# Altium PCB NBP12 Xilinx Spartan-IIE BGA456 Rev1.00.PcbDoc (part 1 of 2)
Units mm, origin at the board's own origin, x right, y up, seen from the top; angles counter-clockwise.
Board outline 69 x 80.99 mm, 4 copper layers (Top Layer, MidLayer1, InternalPlane1, Bottom Layer); 54 components, 265 nets, 866 pads, 396 vias.
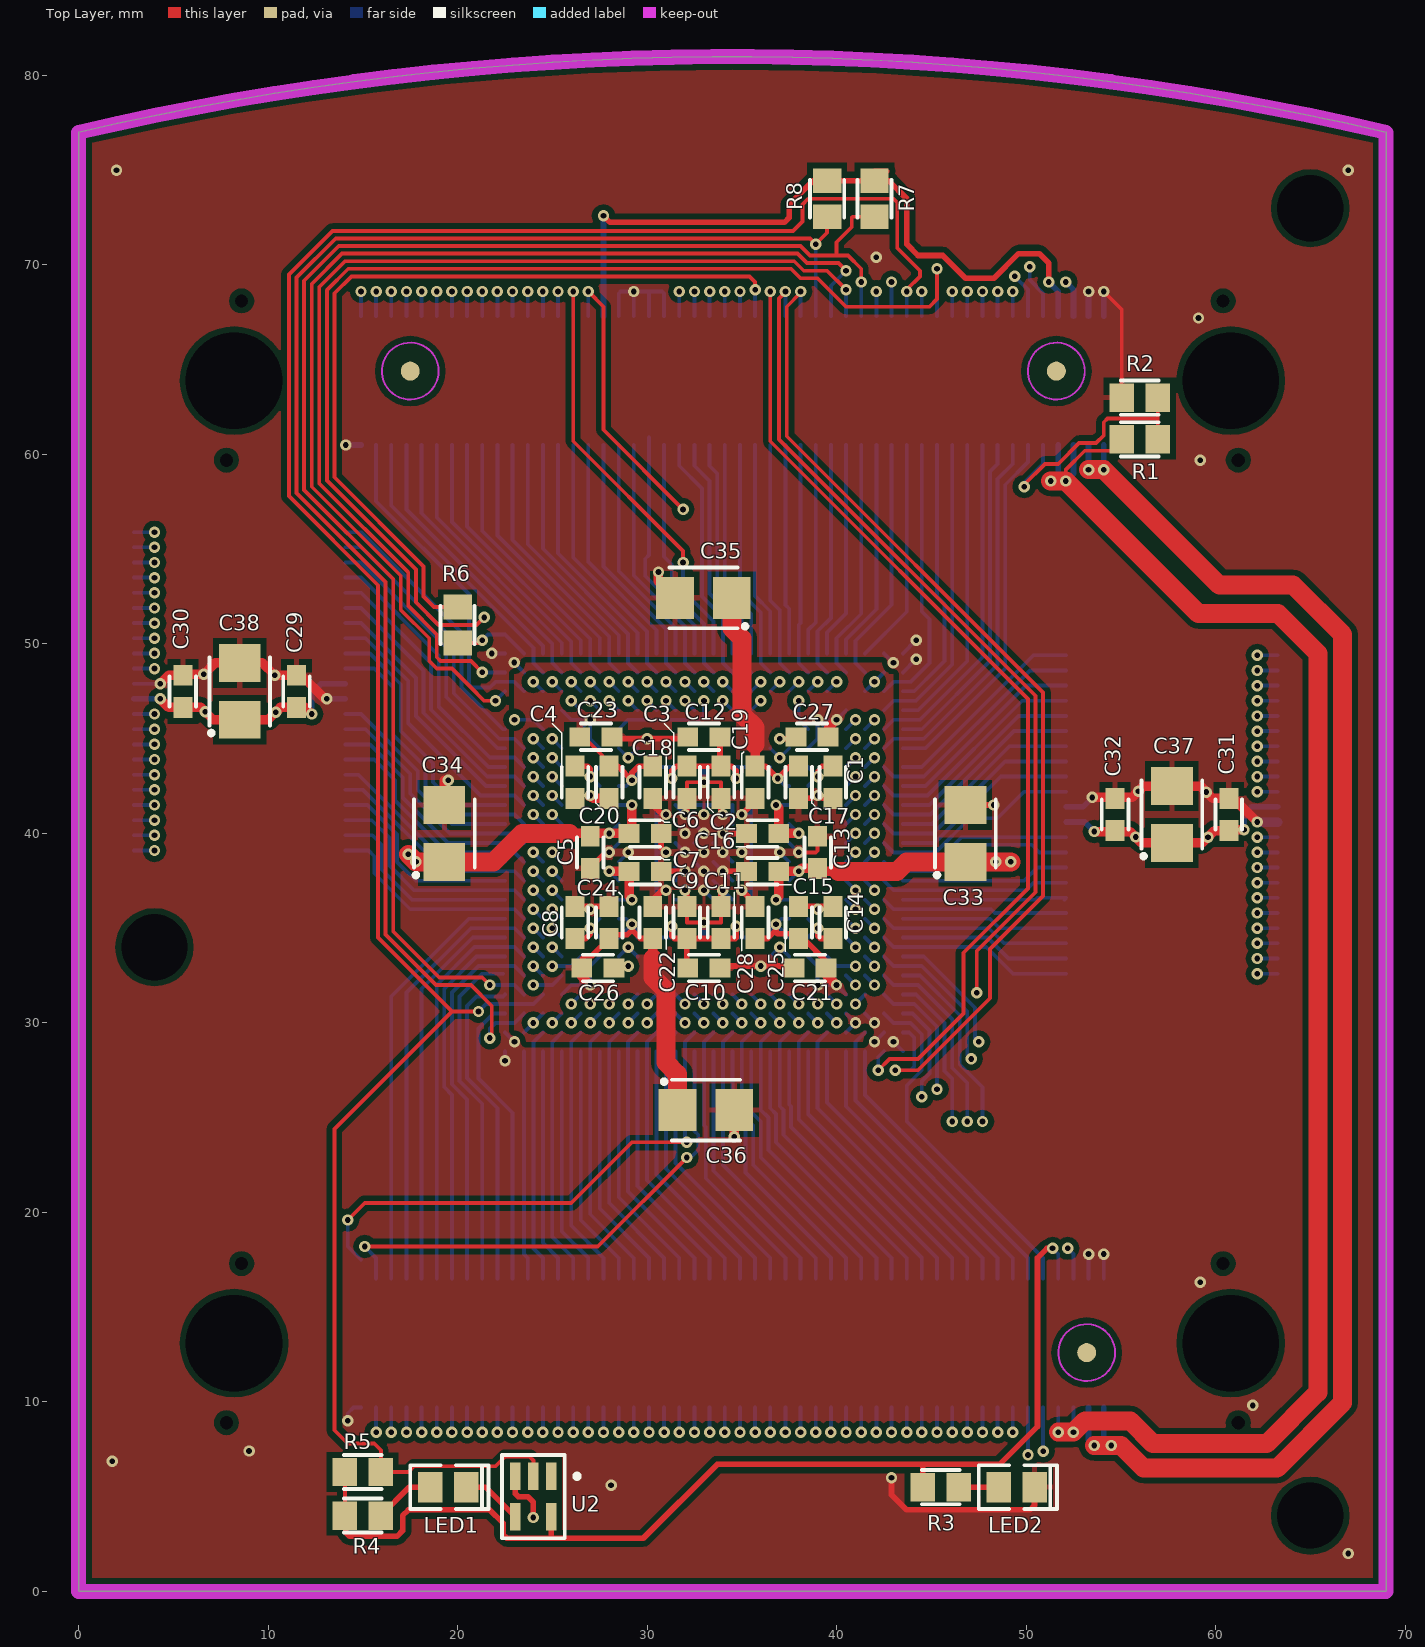
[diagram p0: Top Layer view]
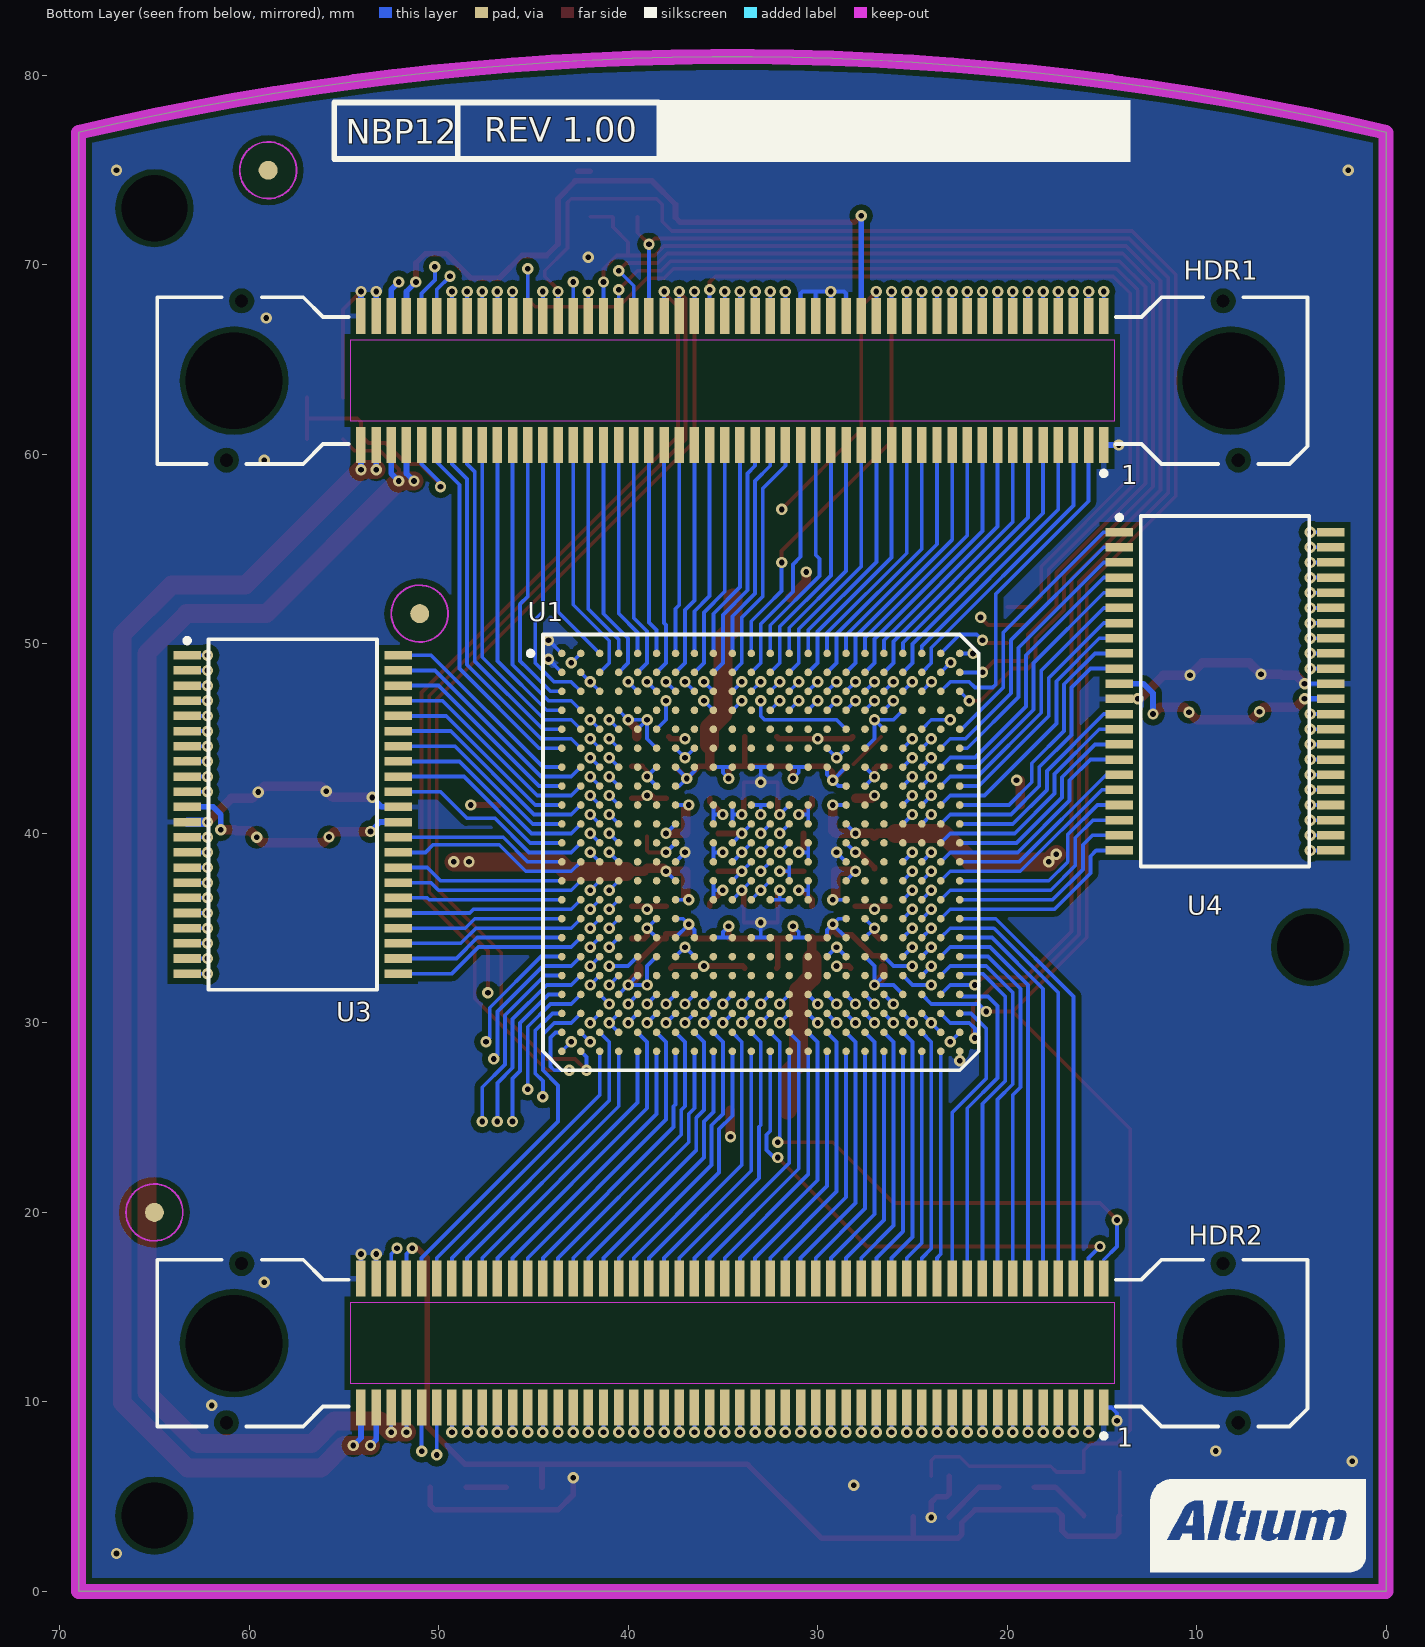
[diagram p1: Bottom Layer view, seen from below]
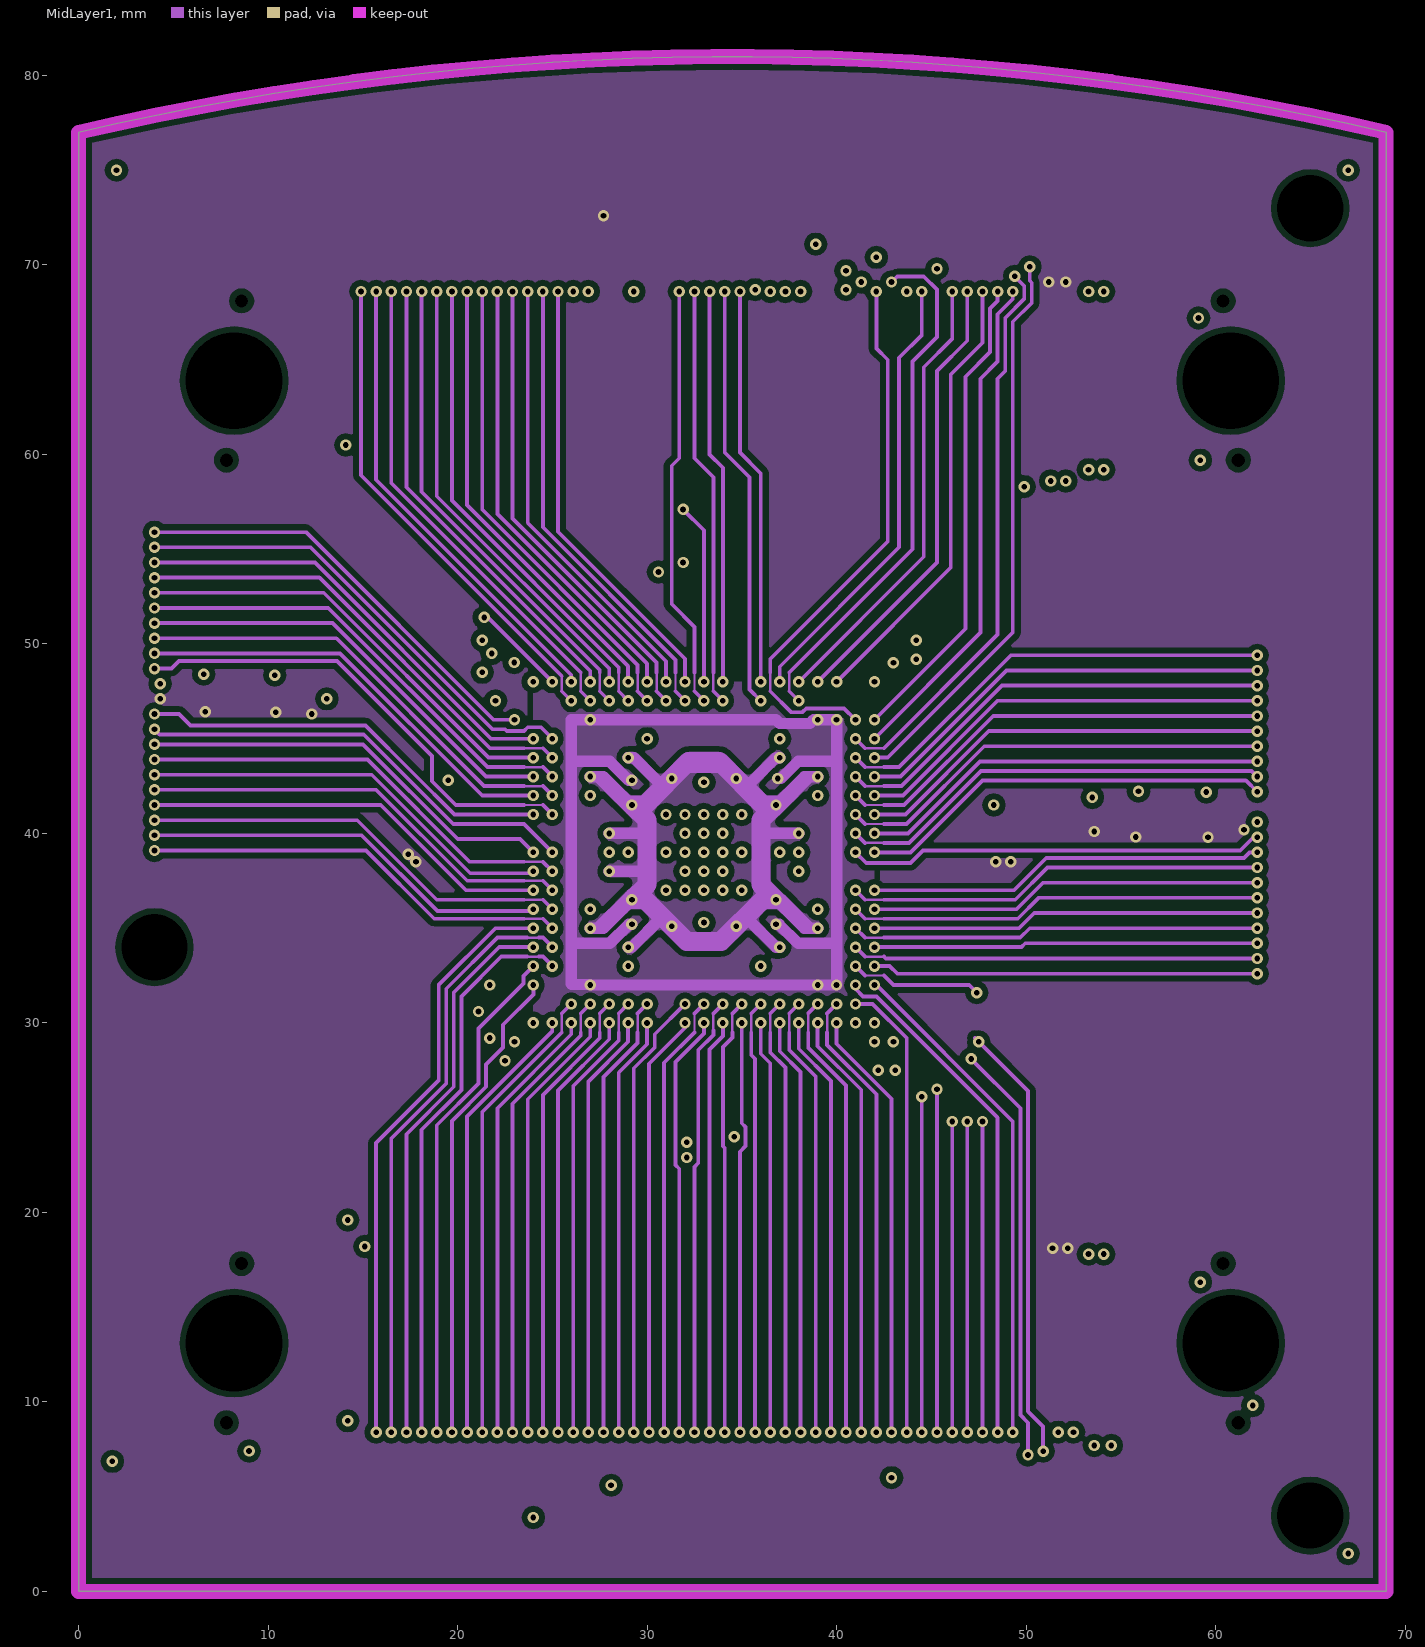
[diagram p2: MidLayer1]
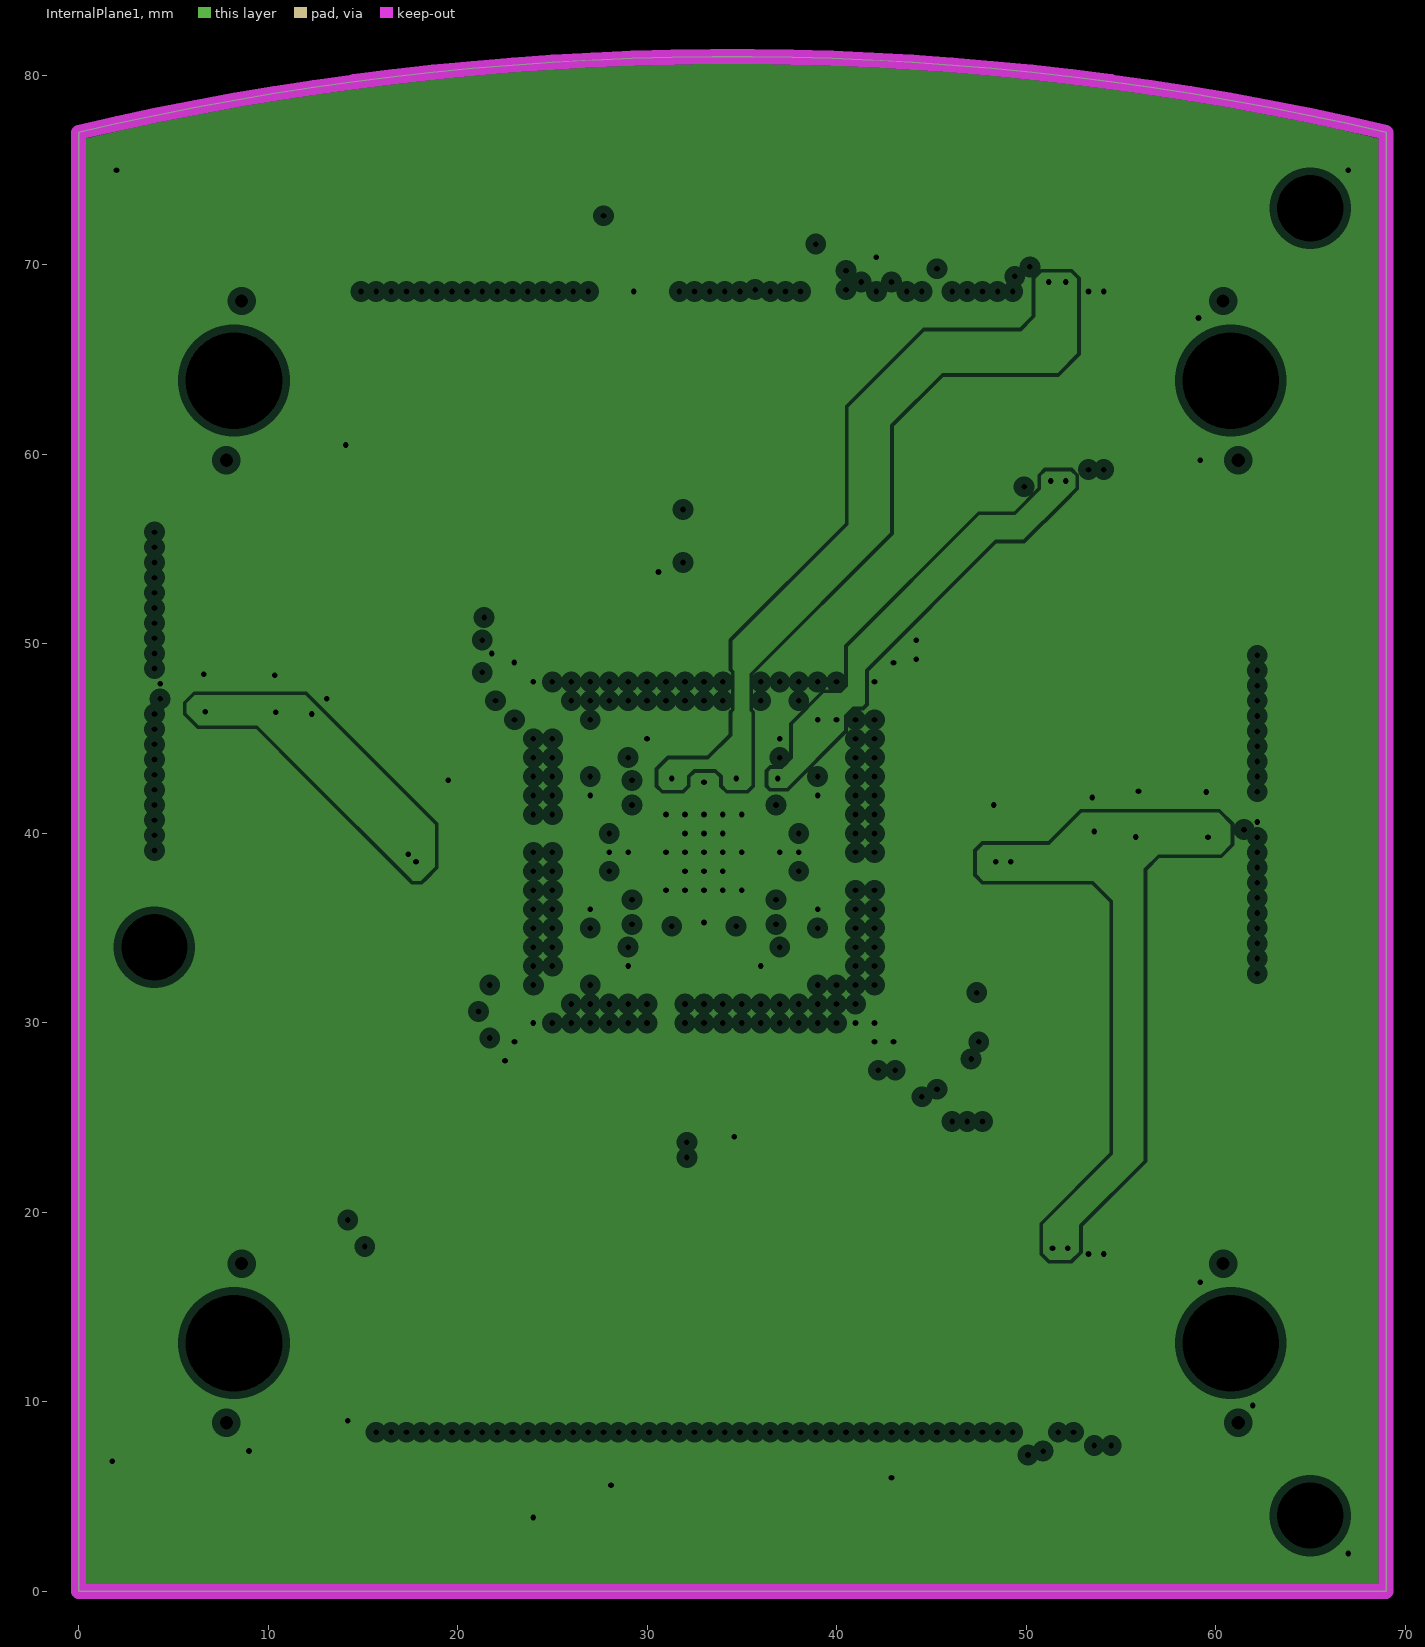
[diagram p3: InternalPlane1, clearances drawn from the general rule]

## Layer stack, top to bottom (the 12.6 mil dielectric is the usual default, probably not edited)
Top Layer: signal copper 0.0356
Dielectric: core 0.32, FR-4, Dk 4.8
MidLayer1: signal copper 0.0356
Dielectric: prepreg 0.32, FR-4, Dk 4.8
InternalPlane1: plane copper 0.0356, net (Multiple Nets)
Dielectric: core 0.32, FR-4, Dk 4.8
Bottom Layer: signal copper 0.0356

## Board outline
0,0 0.001,77 cw(c34.5,-69.801) 69,77 69,0

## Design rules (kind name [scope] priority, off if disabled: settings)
Clearance Clearance_Mid [OnLayer('MidLayer1') and not(InPoly) vs (IsVia)] p1: gap=0.127
Clearance Clearance_Polygons [InPoly] p2: gap=0.3
Clearance Clearance_Std [All] p3: gap=0.2
ComponentClearance [All] p1: gap=0.2 collisioncheckmode=3 verticalgap=0.254 showdistances=FALSE
FabricationTestPointUsage TestPointUsage [All] p1 off: valid=0 allowmultiple=FALSE
FabricationTestpoint Testpoint [All] p1 off: side=3 testpointundercomponent=TRUE minsize=1.016 maxsize=2.54 preferedsize=1.524 minholesize=0 maxholesize=1.016 preferedholesize=0.813 testpointgrid=0.025 allowsidetop=TRUE allowsidebottom=TRUE usegrid=TRUE gridtolerance=0
HoleSize [All] p1: absolutevalues=TRUE maxlimit=5.2 minlimit=0.25 maxpercent=80.000 minpercent=20.000
MinimumAnnularRing [not inpadclass('Mounting Holes')] p1: minimumring=0.051
PlaneClearance [All] p1: clearance=0.4
PlaneConnect [All] p1: planeconnectstyle=Direct reliefexpansion=0.2 reliefentries=4 reliefconductorwidth=0.2 reliefairgap=0.2
PolygonConnect FPGA_Connect [(InComponent('U1') AND InNet('GND'))] p1: connectstyle=NoConnect reliefconductorwidth=0.254 reliefentries=4 polygonreliefangle="90 Angle"
PolygonConnect [All] p2: connectstyle=Relief reliefconductorwidth=0.3 reliefentries=4 polygonreliefangle="90 Angle"
RoutingLayers [All] p1: top layer_v5=TRUE mid layer 1_v5=FALSE bottom layer_v5=TRUE
RoutingVias [All] p1: holewidth=0.3 width=0.6 viastyle="Through Hole" minholewidth=0.3 minwidth=0.6 maxholewidth=0.5 maxwidth=0.9
SMDNeckDown [All] p1: percent=100.000
SilkscreenOverComponentPads [All] p1: minsilkscreentomaskgap=0.254
SolderMaskExpansion SolderMaskExpansion_Vias [IsVia] p1: expansion=-0.15
SolderMaskExpansion [All] p2: expansion=0.1
Width Width_Arc [isarc] p1: maxlimit=0.8 minlimit=0.1 preferedwidth=0.1
Width [All] p2: maxlimit=1.5 minlimit=0.127 preferedwidth=0.2
20 further rules are at their usual default settings.

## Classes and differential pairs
pad class "Mounting Holes": Free-LP HDR1-MH1 HDR1-MH2 HDR1-MH3 HDR1-MH4 HDR1-MH5 HDR1-MH6 HDR2-MH1 HDR2-MH2 HDR2-MH3 HDR2-MH4 HDR2-MH5 HDR2-MH6

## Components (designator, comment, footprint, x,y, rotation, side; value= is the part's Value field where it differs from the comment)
C1 "0.1uF" CC1608-0603 39.8,42.7 r90 top
C2 "0.1uF" CC1608-0603 33.9,42.7 r90 top
C3 "0.1uF" CC1608-0603 32.1,42.7 r90 top
C4 "0.1uF" CC1608-0603 26.2,42.7 r90 top
C5 "0.1uF" CC1608-0603 27,39 r90 top
C6 "0.1uF" CC1608-0603 29.9,40 r180 top
C7 "0.1uF" CC1608-0603 29.9,38 r180 top
C8 "0.1uF" CC1608-0603 26.2,35.3 r270 top
C9 "0.1uF" CC1608-0603 32.1,35.3 r270 top
C10 "0.1uF" CC1608-0603 33,32.9 r180 top
C11 "0.1uF" CC1608-0603 33.9,35.3 r270 top
C12 "0.1uF" CC1608-0603 33,45.1 r0 top
C13 "0.1uF" CC1608-0603 39,39 r270 top
C14 "0.1uF" CC1608-0603 39.8,35.3 r270 top
C15 "0.1uF" CC1608-0603 36.1,38 r0 top
C16 "0.1uF" CC1608-0603 36.1,40 r0 top
C17 "0.1uF" CC1608-0603 38,42.7 r90 top
C18 "0.1uF" CC1608-0603 30.3,42.7 r90 top
C19 "0.1uF" CC1608-0603 35.7,42.7 r90 top
C20 "0.1uF" CC1608-0603 28,42.7 r90 top
C21 "0.1uF" CC1608-0603 38.6,32.9 r0 top
C22 "0.1uF" CC1608-0603 30.3,35.3 r270 top
C23 "0.1uF" CC1608-0603 27.3,45.1 r180 top
C24 "0.1uF" CC1608-0603 28,35.3 r270 top
C25 "0.1uF" CC1608-0603 38,35.3 r270 top
C26 "0.1uF" CC1608-0603 27.4,32.9 r180 top
C27 "0.1uF" CC1608-0603 38.7,45.1 r0 top
C28 "0.1uF" CC1608-0603 35.7,35.3 r270 top
C29 "0.1uF" CC1608-0603 11.5,47.5 r270 top
C30 "0.1uF" CC1608-0603 5.5,47.5 r270 top
C31 "0.1uF" CC1608-0603 60.7,41 r270 top
C32 "0.1uF" CC1608-0603 54.7,41 r270 top
C33 "10uF" MCCT-B 46.8,40 r90 top
C34 "10uF" MCCT-B 19.3,40 r90 top
C35 "10uF" MCCT-B 32.971,52.429 r180 top
C36 "10uF" MCCT-B 33.1,25.4 r0 top
C37 "10uF" MCCT-B 57.7,41 r90 top
C38 "10uF" MCCT-B 8.5,47.5 r90 top
HDR1 "54075-1009" 54075 34.5,63.9 r0 bottom locked
HDR2 "54075-1009" 54075 34.5,13.1 r0 bottom locked
LED1 "HSMG-C670" "SMD _LED" 19.5,5.5 r180 top locked
LED2 "HSMH-C670" "SMD _LED" 49.5,5.5 r180 top locked
R1 "DO NOT INSTALL" CC2012-0805#1 56,60.8 r0 top
R2 "DO NOT INSTALL" CC2012-0805#1 56,63 r180 top
R3 "270R" CC2012-0805#1 45.5,5.5 r0 top
R4 "270R" CC2012-0805#1 15,4 r0 top
R5 "4K7" CC2012-0805#1 15,6.3 r0 top
R6 "100R" CC2012-0805#2 20,51 r90 top
R7 "4K7" CC2012-0805#1 42,73.5 r270 top
R8 "4K7" CC2012-0805#1 39.5,73.5 r270 top
U1 "XC2S600E-6FG456C" FG456 33,39 r180 bottom locked
U2 "SN74AHC1G04DBVR" SO-G5/P.95 24,5 r180 top
U3 "SRAM 512Kx16 TSOP44" SO-G44/P.8 57.7,41 r270 bottom
U4 "SRAM 512Kx16 TSOP44" SO-G44/P.8 8.5,47.5 r270 bottom locked

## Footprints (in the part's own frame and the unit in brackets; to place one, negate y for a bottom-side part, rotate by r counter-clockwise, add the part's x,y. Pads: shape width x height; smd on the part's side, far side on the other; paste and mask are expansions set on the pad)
54075 [mm] "Connector; Docking Station, Receptacle; 100 Position; Vertical"
  rect 0.5x1.9 smd: 1(-19.6,3.4) 2(-19.6,-3.4) 3(-18.8,3.4) 4(-18.8,-3.4) 5(-18,3.4) 6(-18,-3.4) 7(-17.2,3.4) 8(-17.2,-3.4) 9(-16.4,3.4) 10(-16.4,-3.4) 11(-15.6,3.4) 12(-15.6,-3.4) 13(-14.8,3.4) 14(-14.8,-3.4) 15(-14,3.4) 16(-14,-3.4) 17(-13.2,3.4) 18(-13.2,-3.4) 19(-12.4,3.4) 20(-12.4,-3.4) 21(-11.6,3.4) 22(-11.6,-3.4) 23(-10.8,3.4) 24(-10.8,-3.4) 25(-10,3.4) 26(-10,-3.4) 27(-9.2,3.4) 28(-9.2,-3.4) 29(-8.4,3.4) 30(-8.4,-3.4) 31(-7.6,3.4) 32(-7.6,-3.4) 33(-6.8,3.4) 34(-6.8,-3.4) 35(-6,3.4) 36(-6,-3.4) 37(-5.2,3.4) 38(-5.2,-3.4) 39(-4.4,3.4) 40(-4.4,-3.4) 41(-3.6,3.4) 42(-3.6,-3.4) 43(-2.8,3.4) 44(-2.8,-3.4) 45(-2,3.4) 46(-2,-3.4) 47(-1.2,3.4) 48(-1.2,-3.4) 49(-0.4,3.4) 50(-0.4,-3.4) 51(0.4,3.4) 52(0.4,-3.4) 53(1.2,3.4) 54(1.2,-3.4) 55(2,3.4) 56(2,-3.4) 57(2.8,3.4) 58(2.8,-3.4) 59(3.6,3.4) 60(3.6,-3.4) 61(4.4,3.4) 62(4.4,-3.4) 63(5.2,3.4) 64(5.2,-3.4) 65(6,3.4) 66(6,-3.4) 67(6.8,3.4) 68(6.8,-3.4) 69(7.6,3.4) 70(7.6,-3.4) 71(8.4,3.4) 72(8.4,-3.4) 73(9.2,3.4) 74(9.2,-3.4) 75(10,3.4) 76(10,-3.4) 77(10.8,3.4) 78(10.8,-3.4) 79(11.6,3.4) 80(11.6,-3.4) 81(12.4,3.4) 82(12.4,-3.4) 83(13.2,3.4) 84(13.2,-3.4) 85(14,3.4) 86(14,-3.4) 87(14.8,3.4) 88(14.8,-3.4) 89(15.6,3.4) 90(15.6,-3.4) 91(16.4,3.4) 92(16.4,-3.4) 93(17.2,3.4) 94(17.2,-3.4) 95(18,3.4) 96(18,-3.4) 97(18.8,3.4) 98(18.8,-3.4) 99(19.6,3.4) 100(19.6,-3.4)
  round 0.5 hole 0.7 unplated: MH1(-26.7,4.2) MH2(-25.9,-4.2) MH3(26.7,4.2) MH4(25.9,-4.2)
  round 4.8 hole 5.1 unplated: MH5(-26.3,0) MH6(26.3,0)
  Top Layer keep-out region: -20.15,2.15 20.15,2.15 20.15,-2.15 -20.15,-2.15
  silkscreen extent -30.35,-4.4 30.35,5.02
CC1608-0603 [mm]
  rect 1.1x1 smd: 1(-0.85,0) 2(0.85,0)
  silkscreen extent -0.8,-0.7 0.8,0.7
CC2012-0805#1 [mm]
  rect 1.3x1.5 smd: 1(-0.95,0) 2(0.95,0)
  silkscreen extent -1,-0.9 1,0.9
CC2012-0805#2 [mm]
  rect 1.3x1.5 smd: 1(-0.95,0.003) 2(0.95,0.003)
  silkscreen extent -1,-0.9 1,0.9
FG456 [mm] "456-Ball Fine Pitch Ball Grid Array (FG456)"
  round 0.4 smd: A1(-10.5,10.5) A2(-9.5,10.5) A3(-8.5,10.5) A4(-7.5,10.5) A5(-6.5,10.5) A6(-5.5,10.5) A7(-4.5,10.5) A8(-3.5,10.5) A9(-2.5,10.5) A10(-1.5,10.5) A11(-0.5,10.5) A12(0.5,10.5) A13(1.5,10.5) A14(2.5,10.5) A15(3.5,10.5) A16(4.5,10.5) A17(5.5,10.5) A18(6.5,10.5) A19(7.5,10.5) A20(8.5,10.5) A21(9.5,10.5) A22(10.5,10.5) AA1(-10.5,-9.5) AA2(-9.5,-9.5) AA3(-8.5,-9.5) AA4(-7.5,-9.5) AA5(-6.5,-9.5) AA6(-5.5,-9.5) AA7(-4.5,-9.5) AA8(-3.5,-9.5) AA9(-2.5,-9.5) AA10(-1.5,-9.5) AA11(-0.5,-9.5) AA12(0.5,-9.5) AA13(1.5,-9.5) AA14(2.5,-9.5) AA15(3.5,-9.5) AA16(4.5,-9.5) AA17(5.5,-9.5) AA18(6.5,-9.5) AA19(7.5,-9.5) AA20(8.5,-9.5) AA21(9.5,-9.5) AA22(10.5,-9.5) AB1(-10.5,-10.5) AB2(-9.5,-10.5) AB3(-8.5,-10.5) AB4(-7.5,-10.5) AB5(-6.5,-10.5) AB6(-5.5,-10.5) AB7(-4.5,-10.5) AB8(-3.5,-10.5) AB9(-2.5,-10.5) AB10(-1.5,-10.5) AB11(-0.5,-10.5) AB12(0.5,-10.5) AB13(1.5,-10.5) AB14(2.5,-10.5) AB15(3.5,-10.5) AB16(4.5,-10.5) AB17(5.5,-10.5) AB18(6.5,-10.5) AB19(7.5,-10.5) AB20(8.5,-10.5) AB21(9.5,-10.5) AB22(10.5,-10.5) B1(-10.5,9.5) B2(-9.5,9.5) B3(-8.5,9.5) B4(-7.5,9.5) B5(-6.5,9.5) B6(-5.5,9.5) B7(-4.5,9.5) B8(-3.5,9.5) B9(-2.5,9.5) B10(-1.5,9.5) B11(-0.5,9.5) B12(0.5,9.5) B13(1.5,9.5) B14(2.5,9.5) B15(3.5,9.5) B16(4.5,9.5) B17(5.5,9.5) B18(6.5,9.5) B19(7.5,9.5) B20(8.5,9.5) B21(9.5,9.5) B22(10.5,9.5) C1(-10.5,8.5) C2(-9.5,8.5) C3(-8.5,8.5) C4(-7.5,8.5) C5(-6.5,8.5) C6(-5.5,8.5) C7(-4.5,8.5) C8(-3.5,8.5) C9(-2.5,8.5) C10(-1.5,8.5) C11(-0.5,8.5) C12(0.5,8.5) C13(1.5,8.5) C14(2.5,8.5) C15(3.5,8.5) C16(4.5,8.5) C17(5.5,8.5) C18(6.5,8.5) C19(7.5,8.5) C20(8.5,8.5) C21(9.5,8.5) C22(10.5,8.5) D1(-10.5,7.5) D2(-9.5,7.5) D3(-8.5,7.5) D4(-7.5,7.5) D5(-6.5,7.5) D6(-5.5,7.5) D7(-4.5,7.5) D8(-3.5,7.5) D9(-2.5,7.5) D10(-1.5,7.5) D11(-0.5,7.5) D12(0.5,7.5) D13(1.5,7.5) D14(2.5,7.5) D15(3.5,7.5) D16(4.5,7.5) D17(5.5,7.5) D18(6.5,7.5) D19(7.5,7.5) D20(8.5,7.5) D21(9.5,7.5) D22(10.5,7.5) E1(-10.5,6.5) E2(-9.5,6.5) E3(-8.5,6.5) E4(-7.5,6.5) E5(-6.5,6.5) E6(-5.5,6.5) E7(-4.5,6.5) E8(-3.5,6.5) E9(-2.5,6.5) E10(-1.5,6.5) E11(-0.5,6.5) E12(0.5,6.5) E13(1.5,6.5) E14(2.5,6.5) E15(3.5,6.5) E16(4.5,6.5) E17(5.5,6.5) E18(6.5,6.5) E19(7.5,6.5) E20(8.5,6.5) E21(9.5,6.5) E22(10.5,6.5) F1(-10.5,5.5) F2(-9.5,5.5) F3(-8.5,5.5) F4(-7.5,5.5) F5(-6.5,5.5) F6(-5.5,5.5) F7(-4.5,5.5) F8(-3.5,5.5) F9(-2.5,5.5) F10(-1.5,5.5) F11(-0.5,5.5) F12(0.5,5.5) F13(1.5,5.5) F14(2.5,5.5) F15(3.5,5.5) F16(4.5,5.5) F17(5.5,5.5) F18(6.5,5.5) F19(7.5,5.5) F20(8.5,5.5) F21(9.5,5.5) F22(10.5,5.5) G1(-10.5,4.5) G2(-9.5,4.5) G3(-8.5,4.5) G4(-7.5,4.5) G5(-6.5,4.5) G6(-5.5,4.5) G7(-4.5,4.5) G8(-3.5,4.5) G9(-2.5,4.5) G10(-1.5,4.5) G11(-0.5,4.5) G12(0.5,4.5) G13(1.5,4.5) G14(2.5,4.5) G15(3.5,4.5) G16(4.5,4.5) G17(5.5,4.5) G18(6.5,4.5) G19(7.5,4.5) G20(8.5,4.5) G21(9.5,4.5) G22(10.5,4.5) H1(-10.5,3.5) H2(-9.5,3.5) H3(-8.5,3.5) H4(-7.5,3.5) H5(-6.5,3.5) H6(-5.5,3.5) H7(-4.5,3.5) H16(4.5,3.5) H17(5.5,3.5) H18(6.5,3.5) H19(7.5,3.5) H20(8.5,3.5) H21(9.5,3.5) H22(10.5,3.5) J1(-10.5,2.5) J2(-9.5,2.5) J3(-8.5,2.5) J4(-7.5,2.5) J5(-6.5,2.5) J6(-5.5,2.5) J7(-4.5,2.5) J9(-2.5,2.5) J10(-1.5,2.5) J11(-0.5,2.5) J12(0.5,2.5) J13(1.5,2.5) J14(2.5,2.5) J16(4.5,2.5) J17(5.5,2.5) J18(6.5,2.5) J19(7.5,2.5) J20(8.5,2.5) J21(9.5,2.5) J22(10.5,2.5) K1(-10.5,1.5) K2(-9.5,1.5) K3(-8.5,1.5) K4(-7.5,1.5) K5(-6.5,1.5) K6(-5.5,1.5) K7(-4.5,1.5) K9(-2.5,1.5) K10(-1.5,1.5) K11(-0.5,1.5) K12(0.5,1.5) K13(1.5,1.5) K14(2.5,1.5) K16(4.5,1.5) K17(5.5,1.5) K18(6.5,1.5) K19(7.5,1.5) K20(8.5,1.5) K21(9.5,1.5) K22(10.5,1.5) L1(-10.5,0.5) L2(-9.5,0.5) L3(-8.5,0.5) L4(-7.5,0.5) L5(-6.5,0.5) L6(-5.5,0.5) L7(-4.5,0.5) L9(-2.5,0.5) L10(-1.5,0.5) L11(-0.5,0.5) L12(0.5,0.5) L13(1.5,0.5) L14(2.5,0.5) L16(4.5,0.5) L17(5.5,0.5) L18(6.5,0.5) L19(7.5,0.5) L20(8.5,0.5) L21(9.5,0.5) L22(10.5,0.5) M1(-10.5,-0.5) M2(-9.5,-0.5) M3(-8.5,-0.5) M4(-7.5,-0.5) M5(-6.5,-0.5) M6(-5.5,-0.5) M7(-4.5,-0.5) M9(-2.5,-0.5) M10(-1.5,-0.5) M11(-0.5,-0.5) M12(0.5,-0.5) M13(1.5,-0.5) M14(2.5,-0.5) M16(4.5,-0.5) M17(5.5,-0.5) M18(6.5,-0.5) M19(7.5,-0.5) M20(8.5,-0.5) M21(9.5,-0.5) M22(10.5,-0.5) N1(-10.5,-1.5) N2(-9.5,-1.5) N3(-8.5,-1.5) N4(-7.5,-1.5) N5(-6.5,-1.5) N6(-5.5,-1.5) N7(-4.5,-1.5) N9(-2.5,-1.5) N10(-1.5,-1.5) N11(-0.5,-1.5) N12(0.5,-1.5) N13(1.5,-1.5) N14(2.5,-1.5) N16(4.5,-1.5) N17(5.5,-1.5) N18(6.5,-1.5) N19(7.5,-1.5) N20(8.5,-1.5) N21(9.5,-1.5) N22(10.5,-1.5) P1(-10.5,-2.5) P2(-9.5,-2.5) P3(-8.5,-2.5) P4(-7.5,-2.5) P5(-6.5,-2.5) P6(-5.5,-2.5) P7(-4.5,-2.5) P9(-2.5,-2.5) P10(-1.5,-2.5) P11(-0.5,-2.5) P12(0.5,-2.5) P13(1.5,-2.5) P14(2.5,-2.5) P16(4.5,-2.5) P17(5.5,-2.5) P18(6.5,-2.5) P19(7.5,-2.5) P20(8.5,-2.5) P21(9.5,-2.5) P22(10.5,-2.5) R1(-10.5,-3.5) R2(-9.5,-3.5) R3(-8.5,-3.5) R4(-7.5,-3.5) R5(-6.5,-3.5) R6(-5.5,-3.5) R7(-4.5,-3.5) R16(4.5,-3.5) R17(5.5,-3.5) R18(6.5,-3.5) R19(7.5,-3.5) R20(8.5,-3.5) R21(9.5,-3.5) R22(10.5,-3.5) T1(-10.5,-4.5) T2(-9.5,-4.5) T3(-8.5,-4.5) T4(-7.5,-4.5) T5(-6.5,-4.5) T6(-5.5,-4.5) T7(-4.5,-4.5) T8(-3.5,-4.5) T9(-2.5,-4.5) T10(-1.5,-4.5) T11(-0.5,-4.5) T12(0.5,-4.5) T13(1.5,-4.5) T14(2.5,-4.5) T15(3.5,-4.5) T16(4.5,-4.5) T17(5.5,-4.5) T18(6.5,-4.5) T19(7.5,-4.5) T20(8.5,-4.5) T21(9.5,-4.5) T22(10.5,-4.5) U1(-10.5,-5.5) U2(-9.5,-5.5) U3(-8.5,-5.5) U4(-7.5,-5.5) U5(-6.5,-5.5) U6(-5.5,-5.5) U7(-4.5,-5.5) U8(-3.5,-5.5) U9(-2.5,-5.5) U10(-1.5,-5.5) U11(-0.5,-5.5) U12(0.5,-5.5) U13(1.5,-5.5) U14(2.5,-5.5) U15(3.5,-5.5) U16(4.5,-5.5) U17(5.5,-5.5) U18(6.5,-5.5) U19(7.5,-5.5) U20(8.5,-5.5) U21(9.5,-5.5) U22(10.5,-5.5) V1(-10.5,-6.5) V2(-9.5,-6.5) V3(-8.5,-6.5) V4(-7.5,-6.5) V5(-6.5,-6.5) V6(-5.5,-6.5) V7(-4.5,-6.5) V8(-3.5,-6.5) V9(-2.5,-6.5) V10(-1.5,-6.5) V11(-0.5,-6.5) V12(0.5,-6.5) V13(1.5,-6.5) V14(2.5,-6.5) V15(3.5,-6.5) V16(4.5,-6.5) V17(5.5,-6.5) V18(6.5,-6.5) V19(7.5,-6.5) V20(8.5,-6.5) V21(9.5,-6.5) V22(10.5,-6.5) W1(-10.5,-7.5) W2(-9.5,-7.5) W3(-8.5,-7.5) W4(-7.5,-7.5) W5(-6.5,-7.5) W6(-5.5,-7.5) W7(-4.5,-7.5) W8(-3.5,-7.5) W9(-2.5,-7.5) W10(-1.5,-7.5) W11(-0.5,-7.5) W12(0.5,-7.5) W13(1.5,-7.5) W14(2.5,-7.5) W15(3.5,-7.5) W16(4.5,-7.5) W17(5.5,-7.5) W18(6.5,-7.5) W19(7.5,-7.5) W20(8.5,-7.5) W21(9.5,-7.5) W22(10.5,-7.5) Y1(-10.5,-8.5) Y2(-9.5,-8.5) Y3(-8.5,-8.5) Y4(-7.5,-8.5) Y5(-6.5,-8.5) Y6(-5.5,-8.5) Y7(-4.5,-8.5) Y8(-3.5,-8.5) Y9(-2.5,-8.5) Y10(-1.5,-8.5) Y11(-0.5,-8.5) Y12(0.5,-8.5) Y13(1.5,-8.5) Y14(2.5,-8.5) Y15(3.5,-8.5) Y16(4.5,-8.5) Y17(5.5,-8.5) Y18(6.5,-8.5) Y19(7.5,-8.5) Y20(8.5,-8.5) Y21(9.5,-8.5) Y22(10.5,-8.5)
  silkscreen extent -12.28,-11.5 11.5,11.5
MCCT-B [mm]
  rect 2x2.2 smd: 1(-1.5,0) 2(1.5,0)
  silkscreen extent -2.3,-1.6 1.8,1.6
"SMD _LED" [mm]
  rect 1.3x1.6 smd: 1(0.95,0) 2(-0.95,0)
  silkscreen extent -2.13,-1.15 2,1.15
SO-G5/P.95 [mm]
  rect 0.55x1.45 smd: 1(-0.95,-1.075) 2(0,-1.075) 3(0.95,-1.075) 4(0.95,1.075) 5(-0.95,1.075)
  silkscreen extent -2.43,-2.2 1.65,2.2
SO-G44/P.8 [mm]
  rect 0.45x1.45 smd: 1(-8.4,-5.575) 2(-7.6,-5.575) 3(-6.8,-5.575) 4(-6,-5.575) 5(-5.2,-5.575) 6(-4.4,-5.575) 7(-3.6,-5.575) 8(-2.8,-5.575) 9(-2,-5.575) 10(-1.2,-5.575) 11(-0.4,-5.575) 12(0.4,-5.575) 13(1.2,-5.575) 14(2,-5.575) 15(2.8,-5.575) 16(3.6,-5.575) 17(4.4,-5.575) 18(5.2,-5.575) 19(6,-5.575) 20(6.8,-5.575) 21(7.6,-5.575) 22(8.4,-5.575) 23(8.4,5.575) 24(7.6,5.575) 25(6.8,5.575) 26(6,5.575) 27(5.2,5.575) 28(4.4,5.575) 29(3.6,5.575) 30(2.8,5.575) 31(2,5.575) 32(1.2,5.575) 33(0.4,5.575) 34(-0.4,5.575) 35(-1.2,5.575) 36(-2,5.575) 37(-2.8,5.575) 38(-3.6,5.575) 39(-4.4,5.575) 40(-5.2,5.575) 41(-6,5.575) 42(-6.8,5.575) 43(-7.6,5.575) 44(-8.4,5.575)
  silkscreen extent -9.3,-5.7 9.25,4.45

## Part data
C1 C2 C3 C4 C5 C6 C7 C8 C9 C10 C11 C12 C13 C14 C15 C16 C17 C18 C19 C20 C21 C22 C23 C24 C25 C26 C27 C28 C29 C30 C31 C32: library part CAP, "Capacitor"
C33 C34 C35 C36 C37 C38: library part CAP_POLAR, "Polar Capacitor"
HDR1 HDR2: "Board-to-Board, Docking Station, 0.80mm (.031\") Pitch, Shielded Receptacle, Vertical, Ultra Low Profile, SMT"
LED1: library part HSMX-C670, "GREEN AS AlGaAs SMD LED"
LED2: library part HSMX-C670, "RED AS AlGaAs SMD LED"
R1 R2 R3 R4 R5 R6 R7 R8: library part RES, "Resistor"
U1: "Spartan-IIE 1.8V FPGA, 456-Ball FBGA, Standard Performance, Commercial Grade"
U2: "Single Gate Inverter"
U3 U4: "512Kx16Bit SRAM TSOP44"

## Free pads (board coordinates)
  round 1 smd far side mask+1: FID1(59,75) FID2(51,51.6) FID3(65,20)
  round 1 smd mask+1: FID5(17.5,64.4) FID6(51.6,64.4) FID7(53.2,12.6)
  round 3.2 hole 3.5 unplated: LP(4,34) LP(65,4) LP(65,73)

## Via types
v1: diameter 0.6, hole 0.3, Top Layer to Bottom Layer, tented top, 396 vias

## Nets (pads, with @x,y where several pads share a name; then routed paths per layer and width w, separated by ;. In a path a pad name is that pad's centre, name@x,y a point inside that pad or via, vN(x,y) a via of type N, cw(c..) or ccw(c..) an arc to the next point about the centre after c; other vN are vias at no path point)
5V: HDR1.97 HDR1.99 HDR2.97 HDR2.99 | length 79.5
  Top Layer w1: v1(53.3,59.2) v1(54.1,59.2) 60.2,53.1 64.1,53.1 66.7,50.5 66.7,9.954 63.246,6.5 56.2,6.5 55,7.7 v1(53.6,7.7)
  Bottom Layer w0.3: HDR2.97@53.3,9.7 53.3,8 v1(53.6,7.7) ; v1(53.3,59.2) HDR1.97@53.3,60.5 ; HDR2.99@54.1,9.7 54.1,8.1 v1(54.5,7.7) ; v1(54.1,59.2) HDR1.99@54.1,60.5
AUDIO_SPI_CSN: HDR1.11 U1.A19 | length 13.7
  Bottom Layer w0.2: HDR1.11@18.9,60.5 18.9,56.666 25.5,50.066 U1.A19@25.5,49.5
BLUE0: HDR1.14 U1.D15 | length 27.5
  MidLayer1 w0.127: 28.5,47.5 28.5,48.5
  MidLayer1 w0.2: v1(19.7,68.6) 19.7,57.563 28.5,48.763 28.5,48.5 ; 28.5,47.5 v1(29,47)
  Bottom Layer w0.2: HDR1.14@19.7,67.3 v1(19.7,68.6) ; v1(29,47) U1.D15@29.5,46.5
BLUE1: HDR1.16 U1.C15 | length 26.1
  MidLayer1 w0.2: v1(20.5,68.6) 20.5,57.328 29,48.828 v1(29,48)
  Bottom Layer w0.2: HDR1.16@20.5,67.3 v1(20.5,68.6) ; v1(29,48) U1.C15@29.5,47.5
BOC_CTS: HDR1.13 U1.B18 | length 14.8
  Bottom Layer w0.2: HDR1.13@19.7,60.5 19.7,56.431 26,50.131 26,49 U1.B18@26.5,48.5
BOC_RTS: HDR1.17 U1.B17 | length 14.6
  Bottom Layer w0.2: HDR1.17@21.3,60.5 21.3,55.963 27,50.263 27,49 U1.B17@27.5,48.5
BOC_RX: HDR1.19 U1.A17 | length 13.2
  Bottom Layer w0.2: HDR1.19@22.1,60.5 22.1,55.728 27.5,50.328 U1.A17@27.5,49.5
BOC_TX: HDR1.15 U1.A18 | length 13.5
  Bottom Layer w0.2: HDR1.15@20.5,60.5 20.5,56.197 26.5,50.197 U1.A18@26.5,49.5
BUZZER: HDR2.24 U1.AB21 | length 12.1
  Bottom Layer w0.2: U1.AB21@23.5,28.5 23.5,17.8 23.7,17.6 HDR2.24@23.7,16.5
CAN_RXD: HDR1.4 U1.C18 | length 27.1
  MidLayer1 w0.2: v1(15.7,68.6) 15.7,58.666 26,48.366 v1(26,48)
  Bottom Layer w0.2: HDR1.4@15.7,67.3 v1(15.7,68.6) ; v1@26.146,47.854 v1(26,48) U1.C18@26.5,47.5
CAN_TXD: HDR1.2 U1.D18 | length 28.2
  MidLayer1 w0.127: 25.5,47.5 25.5,48.3
  MidLayer1 w0.2: v1(14.9,68.6) 14.9,58.9 25.5,48.3 ; 25.5,47.5 v1(26,47)
  Bottom Layer w0.2: HDR1.2@14.9,67.3 v1(14.9,68.6) ; v1(26,47) U1.D18@26.5,46.5
FPGA_AUX0: HDR1.86 U1.E3 | length 27.3
  MidLayer1 w0.2: v1(42,46) 46.8,50.8 46.8,64.1 48.1,65.4 48.1,67.7 48.5,68.1 v1(48.5,68.6)
  Bottom Layer w0.2: U1.E3@41.5,45.5 v1(42,46) ; HDR1.86@48.5,67.3 v1(48.5,68.6)
FPGA_AUX1: HDR1.88 U1.F3 | length 28.6
  MidLayer1 w0.2: v1(42,45) 47.6,50.6 47.6,64 48.5,64.9 48.5,67.4 49.3,68.2 v1(49.3,68.6)
  Bottom Layer w0.2: U1.F3@41.5,44.5 v1(42,45) ; HDR1.88@49.3,67.3 v1(49.3,68.6)
FPGA_AUX2: HDR1.90 U1.F4 | length 33
  MidLayer1 w0.127: 41.5,44.5 42.5,44.5
  MidLayer1 w0.2: v1(41,45) 41.5,44.5 ; 42.5,44.5 48.5,50.5 48.5,64 48.9,64.4 48.9,67.2 49.9,68.2 49.9,68.9 v1(49.4,69.4)
  Bottom Layer w0.2: U1.F4@40.5,44.5 v1(41,45) ; v1(49.4,69.4) 50.1,68.7 HDR1.90@50.1,67.3
FPGA_AUX3: HDR1.92 U1.G3 | length 33.4
  MidLayer1 w0.2: v1(42,44) 42.7,44 49.3,50.6 49.3,67 50.3,68 50.3,69.066 50.2,69.166 v1(50.2,69.9)
  Bottom Layer w0.2: U1.G3@41.5,43.5 v1(42,44) ; v1(50.2,69.9) 50.2,69.2 50.9,68.5 HDR1.92@50.9,67.3
FPGA_CCLK: HDR1.66 U1.B22 | length 56.4
  Top Layer w0.2: v1(21.3,48.5) 20.7,49.1 19.1,49.1 18.9,49.3 18.9,50.5 17.4,52 17.4,53.763 12.7,58.463 12.7,68.837 14.063,70.2 37.769,70.2 38.269,69.7 39.5,69.7 v1(40.5,68.7)
  Bottom Layer w0.2: v1(21.3,48.5) U1.B22@22.5,48.5 ; HDR1.66@40.5,67.3 v1(40.5,68.7)
FPGA_CLK: HDR2.2 U1.AA12 | length 28
  Top Layer w0.2: v1(14.2,19.6) 15.1,20.5 26,20.5 29.2,23.7 v1(32.1,23.7)
  Bottom Layer w0.2: v1(14.2,19.6) 14.2,18.2 14.9,17.5 ; v1(32.1,23.7) 32,23.8 32,29 U1.AA12@32.5,29.5
FPGA_CLK_1: HDR1.30 U1.A11 | length 23.5
  Top Layer w0.2: v1(26.1,68.6) 26.1,60.7 31.9,54.9 v1(31.9,54.3)
  Bottom Layer w0.2: HDR1.30@26.1,67.3 v1(26.1,68.6) ; v1(31.9,54.3) 31.9,52.8 32.711,51.989 33.5,51.2 U1.A11@33.5,49.5
FPGA_CLK_2: HDR1.32 U1.C11 | length 25.1
  Top Layer w0.2: v1(26.9,68.6) 27.7,67.8 27.7,61.3 v1(31.9,57.1)
  MidLayer1 w0.2: v1(31.9,57.1) 33,56 v1(33,48)
  Bottom Layer w0.2: HDR1.32@26.9,67.3 v1(26.9,68.6) ; v1(33,48) U1.C11@33.5,47.5
FPGA_DIN: HDR1.64 U1.C22 | length 59.5
  Top Layer w0.2: v1(22,47) 21.4,47 20.65,47.75 19.7,48.7 18.9,48.7 18.5,49.1 18.5,50.3 17,51.8 17,53.597 12.3,58.297 12.3,69.003 13.897,70.6 37.934,70.6 38.434,70.1 40.1,70.1 v1(40.5,69.7)
  Bottom Layer w0.2: v1(22,47) U1.C22@22.5,47.5 ; HDR1.64@39.7,67.3 39.7,68.9 v1(40.5,69.7)
FPGA_DONE: HDR1.74 R5.2 U1.W20 U2.2 | length 127.5
  Top Layer w0.2: v1(21.1,30.6) 19.7,30.6 ; U2.2@24,6.075 24,6.9 23.8,7.1 22.5,7.1 22,6.6 17.7,6.6 17.4,6.3 R5.2@15.95,6.3 15.95,7.45 15.6,7.8 14.2,7.8 13.5,8.5 13.5,24.4 19.7,30.6 ; 43.2,71.6 43.2,70.9 ; v1(43.7,68.6) 43.7,68.7 44.4,69.4 44.4,69.7 43.2,70.9 ; 19.7,30.6 15.8,34.5 15.8,53.1 11.1,57.8 11.1,69.5 13.4,71.8 37.7,71.8 38.2,72.3 38.2,73.2 38.5,73.5 43,73.5 43.2,73.3 43.2,70.9
  Bottom Layer w0.2: v1(21.1,30.6) 21.5,31 24,31 U1.W20@24.5,31.5 ; HDR1.74@43.7,67.3 v1(43.7,68.6)
FPGA_INIT: HDR1.68 R7.2 U1.W21 | length 81.9
  Top Layer w0.2: v1(21.7,32) 21.3,32.4 19.031,32.4 16.6,34.831 16.6,53.431 11.9,58.131 11.9,69.169 13.731,71 25.569,71 ; 25.6,71 38.1,71 38.6,70.5 ; 39.3,70.5 39.2,70.5 38.6,70.5 ; 40,70.5 40,71.2 40.8,72 40.8,72.5 40.85,72.55 R7.2@42,72.55 ; v1(41.3,69.1) 41.3,69.8 40.6,70.5 38.6,70.5
  Bottom Layer w0.2: v1(21.7,32) 23,32 U1.W21@23.5,31.5 ; HDR1.68@41.3,67.3 v1(41.3,69.1)
FPGA_M0: HDR1.60 U1.AA1 | length 55.6
  Top Layer w0.2: v1(38.1,68.6) 38.1,68.532 37.368,67.8 37.368,60.964 50.9,47.431 50.9,36.7 48.1,33.9 48.1,31.3 44.3,27.5 v1(43.1,27.5)
  Bottom Layer w0.2: HDR1.60@38.1,67.3 v1(38.1,68.6) ; v1(43.1,27.5) 43.9,27.5 44.1,27.7 44.1,29.234 43.834,29.5 U1.AA1@43.5,29.5
FPGA_M1: HDR1.58 U1.U5 | length 54
  Top Layer w0.2: v1(37.3,68.6) 37.3,68.556 36.968,68.224 36.968,60.798 50.5,47.266 50.5,36.9 47.4,33.8 v1(47.4,31.6)
  MidLayer1 w0.127: 41.5,32.5 42.5,32.5
  MidLayer1 w0.2: v1(41,33) 41.5,32.5 ; 42.5,32.5 43,32 47,32 v1(47.4,31.6)
  Bottom Layer w0.2: HDR1.58@37.3,67.3 v1(37.3,68.6) ; U1.U5@39.5,33.5 40,33 v1(41,33)
FPGA_M2: HDR1.56 U1.AB2 | length 53.3
  Top Layer w0.2: v1(36.5,68.6) 36.5,60.7 50.1,47.1 50.1,37.1 46.7,33.7 46.7,30.5 44.3,28.1 42.8,28.1 v1(42.2,27.5)
  Bottom Layer w0.2: HDR1.56@36.5,67.3 v1(36.5,68.6) ; v1(42.2,27.5) 42.2,28.2 U1.AB2@42.5,28.5
FPGA_PROGRAM: HDR1.62 R8.2 U1.Y21 | length 82
  Top Layer w0.2: v1(21.7,29.2) 21.8,29.3 21.8,30.9 20.7,32 18.866,32 16.2,34.666 16.2,53.266 11.5,57.966 11.5,69.334 13.566,71.4 38.6,71.4 v1(38.9,71.1) 39.5,71.7 R8.2@39.5,72.55
  Bottom Layer w0.2: v1(21.7,29.2) 21.7,29.7 22,30 23,30 U1.Y21@23.5,30.5 ; HDR1.62@38.9,67.3 v1(38.9,71.1)
FPGA_TCK: HDR1.72 U1.E6 | length 31.7
  MidLayer1 w0.127: 37.5,47.5 37.5,48.5
  MidLayer1 w0.2: 37.5,47.5 v1(38,47) ; 37.5,48.5 44,55 44,64.9 45.3,66.2 45.3,68.7 44.6,69.4 43.2,69.4 v1(42.9,69.1)
  Bottom Layer w0.2: v1(38,47) 38,46 U1.E6@38.5,45.5 ; HDR1.72@42.9,67.3 v1@42.9,69.3
FPGA_TDI: HDR1.78 U1.C19 | length 66.2
  Top Layer w0.2: v1(21.4,51.4) 21,51 19,51 17.8,52.2 17.8,53.928 13.1,58.628 13.1,68.672 14.228,69.8 37.603,69.8 38.103,69.3 39,69.3 40.5,67.8 44.9,67.8 45.3,68.2 v1(45.3,69.8)
  MidLayer1 w0.2: v1(21.4,51.4) 21.6,51.4 22.8,50.2 v1(25,48)
  Bottom Layer w0.2: v1(25,48) U1.C19@25.5,47.5 ; HDR1.78@45.3,67.3 v1(45.3,69.8)
FPGA_TDO: HDR1.54 R6.2 | length 44.5
  Top Layer w0.2: R6.2@19.997,51.95 18.75,51.95 18.2,52.5 18.2,54.094 13.5,58.794 13.5,68.506 14.394,69.4 35.4,69.4 35.7,69.1 v1(35.7,68.7)
  Bottom Layer w0.2: HDR1.54@35.7,67.3 v1(35.7,68.7)
FPGA_TDO#: R6.1 U1.A21 | length 4.1
  Top Layer w0.2: R6.1@19.997,50.05 21.15,50.05 v1(21.3,50.2)
  Bottom Layer w0.2: v1(21.3,50.2) 21.6,50.5 22.5,50.5 U1.A21@23.5,49.5
FPGA_TMS: HDR1.70 U1.E4 | length 31.2
  MidLayer1 w0.127: 36.5,47.5 36.5,48.5
  MidLayer1 w0.2: 36.5,47.5 37.6,46.4 38.2,46.4 38.4,46.6 40.4,46.6 v1(41,46) ; 36.5,48.5 36.5,49.2 42.7,55.4 42.7,65 42.1,65.6 v1(42.1,68.6)
  Bottom Layer w0.2: U1.E4@40.5,45.5 v1(41,46) ; HDR1.70@42.1,67.3 v1(42.1,68.6)
GND: C1.1 C2.1 C3.1 C4.1 C5.1 C6.1 C7.1 C8.1 C9.1 C10.1 C11.1 C12.1 C13.1 C14.1 C15.1 C16.1 C17.1 C18.1 C19.1 C20.1 C21.1 C22.1 C23.1 C24.1 C25.1 C26.1 C27.1 C28.1 C29.1 C30.1 C31.1 C32.1 C33.2 C34.2 C35.2 C36.2 C37.2 C38.2 HDR1.1 HDR1.36 HDR1.38 HDR1.40 HDR1.42 HDR1.98 HDR1.100 HDR2.1 HDR2.98 HDR2.100 LED2.2 R2.2 U1.A1 U1.A2 U1.A22 U1.AA2 U1.AA4 U1.AA21 U1.AA22 U1.AB1 U1.AB22 U1.B1 U1.B2 U1.B21 U1.C3 U1.C20 U1.G11 U1.G12 U1.J9 U1.J10 U1.J11 U1.J12 U1.J13 U1.J14 U1.K9 U1.K10 U1.K11 U1.K12 U1.K13 U1.K14 U1.L7 U1.L9 U1.L10 U1.L11 U1.L12 U1.L13 U1.L14 U1.L16 U1.M7 U1.M9 U1.M10 U1.M11 U1.M12 U1.M13 U1.M14 U1.M16 U1.N9 U1.N10 U1.N11 U1.N12 U1.N13 U1.N14 U1.P9 U1.P10 U1.P11 U1.P12 U1.P13 U1.P14 U1.T11 U1.T12 U1.Y3 U1.Y4 U1.Y20 U2.3 U3.12 U3.34 U4.12 U4.34 | length 149.4
  Top Layer w0.2: v1@26.85,41.85 v1(27,42) ; C9.1@32.1,36.15 32.1,35.3 v1(33,35.3) 33.9,35.3 C11.1@33.9,36.15 ; C3.1@32.1,41.85 32.1,42.7 v1(33,42.7) 33.9,42.7 C2.1@33.9,41.85 ; v1(38,39) 38.9,39 39,39.1 C13.1@39,39.85 ; v1(54.1,68.6) 55.05,67.65 R2.2@55.05,63
  Top Layer w0.3: U2.3@23.05,6.075 23.05,5.15 23.2,5 23.7,5 24,4.7 v1(24,3.9) ; C8.1@26.2,36.15 26.85,36.15 v1(27,36) 27.15,36.15 C24.1@28,36.15 ; C5.1@27,38.15 27,38.2 27.8,39 v1(28,39) ; C23.1@28.15,45.1 28.25,45 v1(30,45) 32.05,45 C12.1@32.15,45.1 ; C26.1@28.25,32.9 28.35,33 v1(29,33) ; C22.1@30.3,36.15 30.3,36.5 30.8,37 v1(31,37) ; C18.1@30.3,41.85 30.3,41.5 30.8,41 v1(31,41) ; C7.1@30.75,38 v1(32,38) ; C6.1@30.75,40 30.75,39.25 v1(31,39) ; v1(32,37) 32.1,36.9 C9.1@32.1,36.15 ; v1(32,41) 32.1,41.1 C3.1@32.1,41.85 ; C10.1@33.85,32.9 33.95,33 v1(36,33) 37.65,33 C21.1@37.75,32.9 ; C11.1@33.9,36.15 33.9,36.9 v1(34,37) ; C2.1@33.9,41.85 33.9,41.1 v1(34,41) ; v1(34,38) C15.1@35.25,38 ; v1(34,40) C16.1@35.25,40 ; v1(35,37) 35.7,36.3 C28.1@35.7,36.15 ; v1(35,41) 35.7,41.7 C19.1@35.7,41.85 ; v1(37,45) 37.75,45 C27.1@37.85,45.1 ; C25.1@38,36.15 38.85,36.15 v1(39,36) 39.15,36.15 C14.1@39.8,36.15 ; C17.1@38,41.85 38.6,41.85 38.75,42 39.15,42 39.3,41.85 C1.1@39.8,41.85 ; v1(42.9,6) 42.9,5.1 43.7,4.3 50.2,4.3 50.45,4.55 LED2.2@50.45,5.5 ; C33.2@46.8,41.5 v1(48.3,41.5)
  Top Layer w0.5: v1(4.3,47.9) 4.75,48.35 C30.1@5.5,48.35 5.55,48.4 v1(6.6,48.4) 7.2,49 9.7,49 v1(10.35,48.35) 11.75,48.35 v1@13,47.1 ; C34.2@19.3,41.5 v1@19.3,42.8 ; v1(27,42) 27.15,41.85 C20.1@28,41.85 ; v1(30.6,53.8) 30.6,53.3 C35.2@31.471,52.429 ; v1(34.6,24) C36.2@34.6,25.4 ; v1(53.5,41.9) 55.6,41.9 56.2,42.5 59.2,42.5 59.85,41.85 60.95,41.85 v1(62.2,40.6)
  Bottom Layer w0.2: U4.34@2.925,47.9 v1(4.3,47.9) ; v1(14.2,9) 14.2,9.4 14.5,9.7 HDR2.1@14.9,9.7 ; v1(21.8,49.5) U1.A22@22.5,49.5 ; v1(22.5,28) U1.AB22@22.5,28.5 ; U1.AA22@22.5,29.5 v1(23,29) ; v1(22.981,49.019) U1.B21@23.5,48.5 ; U1.AA21@23.5,29.5 U1.Y20@24.5,30.5 ; v1(23.987,48.013) U1.C20@24.5,47.5 ; v1(28,39) U1.L16@28.5,39.5 ; U1.M16@28.5,38.5 v1(29,39) ; HDR1.36@28.5,67.3 28.5,68.5 28.6,68.6 30.8,68.6 30.9,68.5 HDR1.42@30.9,67.3 ; HDR1.38@29.3,67.3 v1(29.3,68.6) ; HDR1.40@30.1,67.3 30.1,68.6 ; U1.P14@30.5,36.5 U1.N14@30.5,37.5 ; 30.5,37 v1(31,37) ; U1.M14@30.5,38.5 U1.L14@30.5,39.5 ; 30.5,39 v1(31,39) ; U1.K14@30.5,40.5 U1.J14@30.5,41.5 ; 30.6,41 v1(31,41) ; U1.P13@31.5,36.5 U1.P12@32.5,36.5 ; U1.N13@31.5,37.5 U1.M13@31.5,38.5 ; 31.5,38 v1(32,38) ; U1.L13@31.5,39.5 v1(32,39) ; U1.K13@31.5,40.5 v1(32,40) ; U1.J13@31.5,41.5 v1(32,41) ; 32,36.5 v1(32,37) ; U1.T12@32.5,34.5 U1.T11@33.5,34.5 ; U1.N12@32.5,37.5 v1(33,37) U1.P11@33.5,36.5 ; U1.M12@32.5,38.5 v1(33,38) ; U1.L12@32.5,39.5 v1(33,39) ; U1.K12@32.5,40.5 v1(33,40) ; U1.J12@32.5,41.5 U1.J11@33.5,41.5 ; U1.G12@32.5,43.5 U1.G11@33.5,43.5 ; 33,34.5 v1(33,35.3) ; v1(33,41) 33,41.5 ; v1(33,42.7) 33,43.5 ; U1.N11@33.5,37.5 v1(34,37) U1.P10@34.5,36.5 ; U1.M11@33.5,38.5 v1(34,38) U1.N10@34.5,37.5 ; U1.L11@33.5,39.5 v1(34,39) U1.M10@34.5,38.5 ; U1.K11@33.5,40.5 v1(34,40) U1.L10@34.5,39.5 ; v1(34,41) 34.5,41 ; U1.K10@34.5,40.5 U1.J10@34.5,41.5 ; v1(35,37) 35.5,37 ; v1(35,39) 35.5,39 ; v1(35,41) 35.5,41 ; U1.P9@35.5,36.5 U1.N9@35.5,37.5 ; U1.M9@35.5,38.5 U1.L9@35.5,39.5 ; U1.K9@35.5,40.5 U1.J9@35.5,41.5 ; v1(37,39) U1.M7@37.5,38.5 ; U1.L7@37.5,39.5 v1(38,39) ; U1.AA4@40.5,29.5 v1(41,30) U1.Y4@40.5,30.5 ; U1.Y3@41.5,30.5 v1(42,30) ; U1.C3@41.5,47.5 v1(41.999,47.999) U1.B2@42.5,48.5 ; v1(42,29) U1.AA2@42.5,29.5 ; U1.A2@42.5,49.5 v1(43,49) ; v1(43,29) U1.AB1@43.5,28.5 ; U1.B1@43.5,48.5 v1(44.2,49.2) ; U1.A1@43.5,49.5 v1(44.2,50.2) ; HDR2.98@53.3,16.5 v1(53.3,17.8) ; HDR2.100@54.1,16.5 v1(54.1,17.8)
  Bottom Layer w0.3: v1@13,47.1 U4.12@14.075,47.1 ; v1(14.1,60.5) HDR1.1@14.9,60.5 ; U3.34@52.125,41.4 53,41.4 v1(53.5,41.9) ; HDR1.98@53.3,67.3 v1(53.3,68.6) ; HDR1.100@54.1,67.3 v1(54.1,68.6)
  Bottom Layer w0.5: v1(62.2,40.6) U3.12@63.275,40.6
  other v1: 67,2 28.1,5.6 1.778,6.858 8.995,7.409 61.969,9.813 59.2,16.319 24,30 39,42 59.518,42.182 55.934,42.234 19.5,42.8 13.1,47.1 59.2,59.7 59.1,67.2 42.1,70.4 2,75 67,75
GREEN0: HDR1.10 U1.D16 | length 27.7
  MidLayer1 w0.127: 27.5,47.5 27.5,48.5
  MidLayer1 w0.2: v1(18.1,68.6) 18.1,58.031 27.5,48.631 27.5,48.5 ; 27.5,47.5 v1(28,47)
  Bottom Layer w0.2: HDR1.10@18.1,67.3 v1(18.1,68.6) ; v1(28,47) U1.D16@28.5,46.5
GREEN1: HDR1.12 U1.C16 | length 26.4
  MidLayer1 w0.2: v1(18.9,68.6) 18.9,57.797 28,48.697 v1(28,48)
  Bottom Layer w0.2: HDR1.12@18.9,67.3 v1(18.9,68.6) ; v1(28,48) U1.C16@28.5,47.5
HDRIVE: HDR1.18 U1.D14 | length 27.2
  MidLayer1 w0.128: 29.5,47.5 29.5,48.5
  MidLayer1 w0.2: v1(21.3,68.6) 21.3,57.094 29.5,48.894 29.5,48.5 ; 29.5,47.5 v1(30,47)
  Bottom Layer w0.2: HDR1.18@21.3,67.3 v1(21.3,68.6) ; v1(30,47) U1.D14@30.5,46.5
IO0: HDR2.7 U1.U20 | length 31.4
  MidLayer1 w0.2: v1(17.3,8.4) 17.3,24.128 19.8,26.628 19.8,31.6 22.2,34 v1(24,34)
  Bottom Layer w0.2: v1(17.3,8.4) HDR2.7@17.3,9.7 ; v1(24,34) U1.U20@24.5,33.5
IO1: HDR2.9 U1.U18 | length 32.8
  MidLayer1 w0.127: 23.668,33.5 24.3,33.5
  MidLayer1 w0.2: v1(18.1,8.4) 18.1,24.363 20.2,26.463 20.2,31.4 22.3,33.5 23.668,33.5 ; 24.3,33.5 24.332,33.5 24.5,33.5 v1(25,33)
  Bottom Layer w0.2: v1(18.1,8.4) HDR2.9@18.1,9.7 ; v1(25,33) 26,33 U1.U18@26.5,33.5
IO2: HDR2.11 U1.V20 | length 28.9
  MidLayer1 w0.2: v1(18.9,8.4) 18.9,24.597 21.1,26.797 21.1,29.7 23.479,32.079 23.479,32.479 v1(24,33)
  Bottom Layer w0.2: v1(18.9,8.4) HDR2.11@18.9,9.7 ; v1@24.146,32.854 v1(24,33) U1.V20@24.5,32.5
IO3: HDR2.13 U1.V19 | length 28.4
  MidLayer1 w0.2: v1(19.7,8.4) 19.7,24.831 21.5,26.631 21.5,27.8 22.4,28.7 22.4,29.9 24,31.5 v1(24,32)
  Bottom Layer w0.2: v1(19.7,8.4) HDR2.13@19.7,9.7 ; v1(24,32) 25,32 U1.V19@25.5,32.5
IO4: HDR2.15 U1.Y19 | length 25.6
  MidLayer1 w0.2: v1(20.5,8.4) 20.5,24.7 20.5,25.066 25,29.566 v1(25,30)
  Bottom Layer w0.2: v1(20.5,8.4) HDR2.15@20.5,9.7 ; v1@25.108,30.108 v1(25,30) U1.Y19@25.5,30.5
IO5: HDR2.17 U1.W18 | length 26.6
  MidLayer1 w0.127: 25.5,29.5 25.5,30.5
  MidLayer1 w0.2: v1(21.3,8.4) 21.3,25.3 25.5,29.5 ; 25.5,30.5 v1(26,31)
  Bottom Layer w0.2: v1(21.3,8.4) HDR2.17@21.3,9.7 ; v1(26,31) U1.W18@26.5,31.5
IO6: HDR2.19 U1.Y18 | length 25.2
  MidLayer1 w0.2: v1(22.1,8.4) 22.1,25.5 26,29.4 v1(26,30)
  Bottom Layer w0.2: v1(22.1,8.4) HDR2.19@22.1,9.7 ; v1(26,30) U1.Y18@26.5,30.5
IO7: HDR2.21 U1.W17 | length 26.3
  MidLayer1 w0.127: 26.5,29.5 26.5,30.5
  MidLayer1 w0.2: v1(22.9,8.4) 22.9,25.734 26.5,29.334 26.5,29.5 ; 26.5,30.5 v1(27,31)
  Bottom Layer w0.2: v1(22.9,8.4) HDR2.21@22.9,9.7 ; v1(27,31) U1.W17@27.5,31.5
IO8: HDR2.23 U1.Y17 | length 25
  MidLayer1 w0.2: v1(23.7,8.4) 23.7,25.969 27,29.269 v1(27,30)
  Bottom Layer w0.2: v1(23.7,8.4) HDR2.23@23.7,9.7 ; v1(27,30) U1.Y17@27.5,30.5
IO9: HDR2.25 U1.W16 | length 26.1
  MidLayer1 w0.127: 27.5,29.5 27.5,30.5
  MidLayer1 w0.2: v1(24.5,8.4) 24.5,26.203 27.5,29.203 27.5,29.5 ; 27.5,30.5 v1(28,31)
  Bottom Layer w0.2: v1(24.5,8.4) HDR2.25@24.5,9.7 ; v1(28,31) U1.W16@28.5,31.5
IO10: HDR2.27 U1.Y16 | length 24.7
  MidLayer1 w0.2: v1(25.3,8.4) 25.3,26.437 28,29.137 v1(28,30)
  Bottom Layer w0.2: v1(25.3,8.4) HDR2.27@25.3,9.7 ; v1(28,30) U1.Y16@28.5,30.5
IO11: HDR2.29 U1.W15 | length 25.8
  MidLayer1 w0.127: 28.5,29.5 28.5,30.5
  MidLayer1 w0.2: v1(26.1,8.4) 26.1,26.672 28.5,29.072 28.5,29.5 ; 28.5,30.5 v1(29,31)
  Bottom Layer w0.2: v1(26.1,8.4) HDR2.29@26.1,9.7 ; v1(29,31) U1.W15@29.5,31.5
IO12: HDR2.31 U1.Y15 | length 24.5
  MidLayer1 w0.2: v1(26.9,8.4) 26.9,26.906 29,29.006 v1(29,30)
  Bottom Layer w0.2: v1(26.9,8.4) HDR2.31@26.9,9.7 ; v1(29,30) U1.Y15@29.5,30.5
IO13: HDR2.33 U1.W14 | length 25.6
  MidLayer1 w0.127: 29.5,29.5 29.5,30.5
  MidLayer1 w0.2: v1(27.7,8.4) 27.7,27.14 29.5,28.94 29.5,29.5 ; 29.5,30.5 v1(30,31)
  Bottom Layer w0.2: v1(27.7,8.4) HDR2.33@27.7,9.7 ; v1(30,31) U1.W14@30.5,31.5
IO14: HDR2.35 U1.Y14 | length 24.2
  MidLayer1 w0.2: v1(28.5,8.4) 28.5,27.375 30,28.875 v1(30,30)
  Bottom Layer w0.2: v1(28.5,8.4) HDR2.35@28.5,9.7 ; v1(30,30) U1.Y14@30.5,30.5
IO15: HDR2.37 U1.W13 | length 25.7
  MidLayer1 w0.2: v1(29.3,8.4) 29.3,27.609 30.4,28.709 30.4,29.4 v1(32,31)
  Bottom Layer w0.2: v1(29.3,8.4) HDR2.37@29.3,9.7 ; U1.W13@31.5,31.5 v1(32,31)
IO16: HDR2.39 U1.Y13 | length 24.4
  MidLayer1 w0.2: v1(30.1,8.4) 30.1,27.843 32,29.743 v1(32,30)
  Bottom Layer w0.2: v1(30.1,8.4) HDR2.39@30.1,9.7 ; U1.Y13@31.5,30.5 v1(32,30)
IO17: HDR2.41 U1.W12 | length 25.5
  MidLayer1 w0.127: 32.5,29.5 32.5,30.5
  MidLayer1 w0.2: v1(30.9,8.4) 30.9,27.9 32.5,29.5 ; 32.5,30.5 v1(33,31)
  Bottom Layer w0.2: v1(30.9,8.4) HDR2.41@30.9,9.7 ; U1.W12@32.5,31.5 v1(33,31)
IO18: HDR2.43 U1.Y12 | length 24.3
  MidLayer1 w0.2: v1(31.7,8.4) 31.7,22.3 31.5,22.5 31.5,27.934 32.351,28.786 33,29.434 v1(33,30)
  Bottom Layer w0.2: v1(31.7,8.4) HDR2.43@31.7,9.7 ; U1.Y12@32.5,30.5 v1(33,30)
IO19: HDR2.45 U1.W11 | length 25.2
  MidLayer1 w0.127: 33.5,29.6 33.5,30.5
  MidLayer1 w0.2: v1(32.5,8.4) 32.5,22.4 32.7,22.6 32.7,28.569 33.5,29.369 33.5,29.6 ; 33.5,30.5 v1(34,31)
  Bottom Layer w0.2: v1(32.5,8.4) HDR2.45@32.5,9.7 ; U1.W11@33.5,31.5 v1(34,31)
IO20: HDR2.47 U1.Y11 | length 23.9
  MidLayer1 w0.2: v1(33.3,8.4) 33.3,28.603 34,29.303 v1(34,30)
  Bottom Layer w0.2: v1(33.3,8.4) HDR2.47@33.3,9.7 ; U1.Y11@33.5,30.5 v1(34,30)
IO21: HDR2.49 U1.W10 | length 25.1
  MidLayer1 w0.128: 34.5,29.5 34.5,30.5
  MidLayer1 w0.2: v1(34.1,8.4) 34.1,20.6 34.1,23.4 34,23.5 34,28.737 34.5,29.237 34.5,29.5 ; 34.5,30.5 v1(35,31)
  Bottom Layer w0.2: v1(34.1,8.4) HDR2.49@34.1,9.7 ; U1.W10@34.5,31.5 v1(35,31)
IO22: HDR2.51 U1.Y10 | length 23.8
  MidLayer1 w0.2: v1(34.9,8.4) 34.9,23.2 35.2,23.5 35.2,24.5 35,24.7 v1(35,30)
  Bottom Layer w0.2: U1.Y10@34.5,30.5 v1(35,30) ; v1(34.9,8.4) HDR2.51@34.9,9.7
IO23: HDR2.53 U1.W9 | length 24.9
  MidLayer1 w0.127: 35.5,29.5 35.5,30.5
  MidLayer1 w0.2: 35.5,29.5 35.5,28.309 35.7,28.109 v1(35.7,8.4) ; 35.5,30.5 v1(36,31)
  Bottom Layer w0.2: U1.W9@35.5,31.5 v1(36,31) ; v1(35.7,8.4) HDR2.53@35.7,9.7
IO24: HDR2.55 U1.Y9 | length 23.8
  MidLayer1 w0.2: v1(36,30) 36,28.375 36.5,27.875 v1(36.5,8.4)
  Bottom Layer w0.2: U1.Y9@35.5,30.5 v1(36,30) ; v1(36.5,8.4) HDR2.55@36.5,9.7
IO25: HDR2.57 U1.W8 | length 25.1
  MidLayer1 w0.127: 36.5,29.5 36.5,30.5
  MidLayer1 w0.2: 36.5,29.5 36.5,28.44 37.3,27.64 v1(37.3,8.4) ; 36.5,30.5 v1(37,31)
  Bottom Layer w0.2: U1.W8@36.5,31.5 v1(37,31) ; v1(37.3,8.4) HDR2.57@37.3,9.7
IO26: HDR2.59 U1.Y8 | length 24.1
  MidLayer1 w0.2: v1(37,30) 37,28.506 38.1,27.406 v1(38.1,8.4)
  Bottom Layer w0.2: U1.Y8@36.5,30.5 v1(37,30) ; v1(38.1,8.4) HDR2.59@38.1,9.7
IO27: HDR2.61 U1.W7 | length 25.4
  MidLayer1 w0.127: 37.5,29.5 37.5,30.5
  MidLayer1 w0.2: 37.5,29.5 37.5,28.572 38.9,27.172 v1(38.9,8.4) ; 37.5,30.5 v1(38,31)
  Bottom Layer w0.2: U1.W7@37.5,31.5 v1(38,31) ; v1(38.9,8.4) HDR2.61@38.9,9.7
IO28: HDR2.63 U1.Y7 | length 24.3
  MidLayer1 w0.2: v1(38,30) 38,28.637 39.7,26.937 v1(39.7,8.4)
  Bottom Layer w0.2: U1.Y7@37.5,30.5 v1(38,30) ; v1(39.7,8.4) HDR2.63@39.7,9.7
IO29: HDR2.65 U1.W6 | length 25.6
  MidLayer1 w0.127: 38.5,29.5 38.5,30.5
  MidLayer1 w0.2: 38.5,29.5 38.5,28.703 40.5,26.703 v1(40.5,8.4) ; 38.5,30.5 v1(39,31)
  Bottom Layer w0.2: U1.W6@38.5,31.5 v1(39,31) ; v1(40.5,8.4) HDR2.65@40.5,9.7
IO30: HDR2.67 U1.Y6 | length 24.6
  MidLayer1 w0.2: v1(39,30) 39,28.769 41.3,26.469 v1(41.3,8.4)
  Bottom Layer w0.2: U1.Y6@38.5,30.5 v1(39,30) ; v1(41.3,8.4) HDR2.67@41.3,9.7
IO31: HDR2.69 U1.W5 | length 25.9
  MidLayer1 w0.127: 39.5,29.5 39.5,30.5
  MidLayer1 w0.2: 39.5,29.5 39.5,28.834 42.1,26.234 v1(42.1,8.4) ; 39.5,30.5 v1(40,31)
  Bottom Layer w0.2: U1.W5@39.5,31.5 v1(40,31) ; v1(42.1,8.4) HDR2.69@42.1,9.7
IO32: HDR2.71 U1.Y5 | length 24.8
  MidLayer1 w0.2: v1(40,30) 40,28.9 42.9,26 v1(42.9,8.4)
  Bottom Layer w0.2: U1.Y5@39.5,30.5 v1(40,30) ; v1(42.9,8.4) HDR2.71@42.9,9.7
IO33: HDR2.73 U1.W3 | length 26.3
  MidLayer1 w0.2: v1(41,31) 41.9,31 43.7,29.2 v1(43.7,8.4)
  Bottom Layer w0.2: v1(41,31) U1.W3@41.5,31.5 ; v1(43.7,8.4) HDR2.73@43.7,9.7
IO34: HDR2.75 U1.Y1 | length 24.4
  MidLayer1 w0.2: v1(44.5,8.4) v1(44.5,26.1)
  Bottom Layer w0.2: U1.Y1@43.5,30.5 44,30.5 44.9,29.6 44.9,27.334 44.5,26.934 v1(44.5,26.1) ; v1(44.5,8.4) HDR2.75@44.5,9.7
IO35: HDR2.77 U1.W2 | length 26.3
  MidLayer1 w0.2: v1@45.1,26.5 45.3,26.3 v1(45.3,8.4)
  Bottom Layer w0.2: U1.W2@42.5,31.5 43,31 44.1,31 45.3,29.8 v1(45.3,26.5) ; v1(45.3,8.4) HDR2.77@45.3,9.7
JIOA0: HDR1.3 U1.C21 | length 18
  Bottom Layer w0.2: HDR1.3@15.7,60.5 15.7,57.534 20.6,52.634 20.6,47.866 20.766,47.7 21.7,47.7 22,48 23,48 U1.C21@23.5,47.5
JIOA1: HDR1.5 U1.B20 | length 15.3
  Bottom Layer w0.2: HDR1.5@16.5,60.5 16.5,57.3 24,49.8 24,49 U1.B20@24.5,48.5
JIOA2: HDR1.7 U1.A20 | length 14
  Bottom Layer w0.2: HDR1.7@17.3,60.5 17.3,57.1 24.5,49.9 U1.A20@24.5,49.5
JIOA3: HDR1.9 U1.B19 | length 15.1
  Bottom Layer w0.2: HDR1.9@18.1,60.5 18.1,56.9 25,50 25,49 U1.B19@25.5,48.5
JIOB0: HDR1.83 U1.E2 | length 18
  Bottom Layer w0.2: U1.E2@42.5,45.5 43,46 44.4,46 47.7,49.3 HDR1.83@47.7,60.5
JIOB1: HDR1.85 U1.E1 | length 17.7
  Bottom Layer w0.2: U1.E1@43.5,45.5 44.5,45.5 48.1,49.1 48.1,59.1 48.5,59.5 HDR1.85@48.5,60.5
JIOB2: HDR1.87 U1.F2 | length 19.8
  Bottom Layer w0.2: U1.F2@42.5,44.5 43,45 44.6,45 48.5,48.9 48.5,58.7 49.3,59.5 HDR1.87@49.3,60.5
JIOB3: HDR1.89 U1.F1 | length 19.4
  Bottom Layer w0.2: U1.F1@43.5,44.5 44.7,44.5 48.9,48.7 48.9,58.4 50.1,59.6 HDR1.89@50.1,60.5
KBCLOCK: HDR1.22 U1.D13 | length 27
  MidLayer1 w0.127: 30.5,47.5 30.5,48.5
  MidLayer1 w0.2: v1(22.9,68.6) 22.9,56.625 30.5,49.025 30.5,48.5 ; 30.5,47.5 v1(31,47)
  Bottom Layer w0.2: HDR1.22@22.9,67.3 v1(22.9,68.6) ; v1(31,47) U1.D13@31.5,46.5
KBDATA: HDR1.24 U1.C13 | length 25.6
  MidLayer1 w0.2: v1(23.7,68.6) 23.7,56.391 31,49.091 v1(31,48)
  Bottom Layer w0.2: HDR1.24@23.7,67.3 v1(23.7,68.6) ; v1(31,48) U1.C13@31.5,47.5
LCD_BCKL: HDR2.22 U1.Y22 | length 15.7
  Bottom Layer w0.2: U1.Y22@22.5,30.5 21.9,30.5 21.1,29.7 21.1,27.063 22.9,25.263 HDR2.22@22.9,16.5
LCD_E: HDR2.26 U1.AA20 | length 13.4
  Bottom Layer w0.2: HDR2.26@24.5,16.5 24.5,17.6 24,18.1 24,29 U1.AA20@24.5,29.5
LED0: HDR2.60 U1.AB11 | length 13.9
  Bottom Layer w0.2: U1.AB11@33.5,28.5 33.5,22.2 38.1,17.6 HDR2.60@38.1,16.5
LED1: HDR2.62 U1.AA10 | length 15.2
  Bottom Layer w0.2: U1.AA10@34.5,29.5 34,29 34,22.5 38.9,17.6 HDR2.62@38.9,16.5
LED2: HDR2.64 U1.AB10 | length 14.2
  Bottom Layer w0.2: U1.AB10@34.5,28.5 34.5,25.1 35.2,24.4 35.2,22.1 39.7,17.6 HDR2.64@39.7,16.5
LED3: HDR2.66 U1.AA9 | length 15.5
  Bottom Layer w0.2: U1.AA9@35.5,29.5 35,29 35,25.2 35.6,24.6 35.6,22.5 40.5,17.6 HDR2.66@40.5,16.5
LED4: HDR2.68 U1.AB9 | length 14.4
  Bottom Layer w0.2: U1.AB9@35.5,28.5 35.5,25.3 36,24.8 36,22.9 41.3,17.6 HDR2.68@41.3,16.5
LED5: HDR2.70 U1.AA8 | length 15.7
  Bottom Layer w0.2: U1.AA8@36.5,29.5 36,29 36,25.4 36.4,25 36.4,23.3 42.1,17.6 HDR2.70@42.1,16.5
LED6: HDR2.72 U1.AB8 | length 14.7
  Bottom Layer w0.2: U1.AB8@36.5,28.5 36.5,25.5 36.8,25.2 36.8,23.7 42.9,17.6 HDR2.72@42.9,16.5
LED7: HDR2.74 U1.AA7 | length 16
  Bottom Layer w0.2: U1.AA7@37.5,29.5 37,29 37,25.6 37.2,25.4 37.2,24.1 43.7,17.6 HDR2.74@43.7,16.5
MOUSECLOCK: HDR1.26 U1.D12 | length 26.7
  MidLayer1 w0.127: 31.5,47.5 31.5,48.5
  MidLayer1 w0.2: v1(24.5,68.6) 24.5,56.157 31.5,49.157 31.5,48.5 ; 31.5,47.5 v1(32,47)
  Bottom Layer w0.2: HDR1.26@24.5,67.3 v1(24.5,68.6) ; v1(32,47) U1.D12@32.5,46.5
MOUSEDATA: HDR1.28 U1.C12 | length 25.4
  MidLayer1 w0.2: v1(25.3,68.6) 25.3,55.923 32,49.223 v1(32,48)
  Bottom Layer w0.2: HDR1.28@25.3,67.3 v1(25.3,68.6) ; v1(32,48) U1.C12@32.5,47.5
NetLED1_1: LED1.1 R4.2 | length 3.2
  Top Layer w0.3: R4.2@15.95,4 17.45,5.5 LED1.1@18.55,5.5
NetLED1_2: LED1.2 U2.4 | length 3.3
  Top Layer w0.3: LED1.2@20.45,5.5 21.475,5.5 U2.4@23.05,3.925
NetLED2_1: LED2.1 R3.2 | length 2.1
  Top Layer w0.3: R3.2@46.45,5.5 LED2.1@48.55,5.5
NEXUS_TCK: HDR1.82 U1.C6 | length 25.9
  MidLayer1 w0.2: v1(39,48) 45.3,54.3 45.3,64.4 46.9,66 v1(46.9,68.6)
  Bottom Layer w0.2: U1.C6@38.5,47.5 v1(39,48) ; HDR1.82@46.9,67.3 v1(46.9,68.6)
NEXUS_TDI: HDR1.84 U1.C5 | length 25.8
  MidLayer1 w0.2: v1(40,48) 46.029,54.029 46.029,64.229 47.7,65.9 v1(47.7,68.6)
  Bottom Layer w0.2: U1.C5@39.5,47.5 v1(40,48) ; HDR1.84@47.7,67.3 v1(47.7,68.6)
NEXUS_TDO: HDR1.76 U1.C8 | length 25.7
  MidLayer1 w0.2: v1(37,48) 37,48.8 43.3,55.1 43.3,65.1 44.5,66.3 v1(44.5,68.6)
  Bottom Layer w0.2: U1.C8@36.5,47.5 v1(37,48) ; HDR1.76@44.5,67.3 v1(44.5,68.6)
NEXUS_TMS: HDR1.80 U1.C7 | length 26
  MidLayer1 w0.2: v1(38,48) 44.6,54.6 44.6,64.6 46.1,66.1 v1(46.1,68.6)
  Bottom Layer w0.2: U1.C7@37.5,47.5 v1(38,48) ; HDR1.80@46.1,67.3 v1(46.1,68.6)
RAM0_DATA0: HDR2.42 U1.AA16 | length 14.4
  Bottom Layer w0.2: U1.AA16@28.5,29.5 28,29 28,20.5 30.9,17.6 HDR2.42@30.9,16.5
RAM0_DATA1: HDR2.40 U1.AB17 | length 13.1
  Bottom Layer w0.2: U1.AB17@27.5,28.5 27.5,20.2 30.1,17.6 HDR2.40@30.1,16.5
RAM0_DATA2: HDR2.38 U1.AA17 | length 14.2
  Bottom Layer w0.2: U1.AA17@27.5,29.5 27,29 27,19.9 29.3,17.6 HDR2.38@29.3,16.5
RAM0_DATA3: HDR2.36 U1.AB18 | length 12.8
  Bottom Layer w0.2: U1.AB18@26.5,28.5 26.5,19.6 28.5,17.6 HDR2.36@28.5,16.5
RAM0_DATA4: HDR2.34 U1.AA18 | length 13.9
  Bottom Layer w0.2: U1.AA18@26.5,29.5 26,29 26,19.3 27.7,17.6 HDR2.34@27.7,16.5
RAM0_DATA5: HDR2.32 U1.AB19 | length 12.6
  Bottom Layer w0.2: U1.AB19@25.5,28.5 25.5,19 26.9,17.6 HDR2.32@26.9,16.5
RAM0_DATA6: HDR2.30 U1.AA19 | length 13.7
  Bottom Layer w0.2: U1.AA19@25.5,29.5 25,29 25,18.7 26.1,17.6 HDR2.30@26.1,16.5
RAM0_DATA7: HDR2.28 U1.AB20 | length 12.3
  Bottom Layer w0.2: U1.AB20@24.5,28.5 24.5,18.4 25.3,17.6 HDR2.28@25.3,16.5
RAM0_OE: HDR1.41 U1.B11 | length 13.1
  Bottom Layer w0.2: HDR1.41@30.9,60.5 30.9,54.6 31.3,54.2 31.3,52.751 33,51.051 33,49 U1.B11@33.5,48.5
RAM0_WE: HDR1.79 U1.D2 | length 16.2
  Bottom Layer w0.2: U1.D2@42.5,46.5 43,47 44.2,47 46.1,48.9 HDR1.79@46.1,60.5
RAM1_DATA0: HDR1.45 U1.A10 | length 11.8
  Bottom Layer w0.2: HDR1.45@32.5,60.5 32.5,59.4 33.3,58.6 33.3,52.666 34.5,51.466 U1.A10@34.5,49.5
RAM1_DATA1: HDR1.49 U1.A9 | length 11.6
  Bottom Layer w0.2: HDR1.49@34.1,60.5 34.1,52.997 35.5,51.597 U1.A9@35.5,49.5
RAM1_DATA2: HDR1.53 U1.A8 | length 11.3
  Bottom Layer w0.2: HDR1.53@35.7,60.5 35.7,52.528 36.5,51.728 U1.A8@36.5,49.5
RAM1_DATA3: HDR1.57 U1.A7 | length 11.1
  Bottom Layer w0.2: HDR1.57@37.3,60.5 37.3,52.06 37.5,51.86 U1.A7@37.5,49.5
RAM1_DATA4: HDR1.55 U1.B7 | length 12.4
  Bottom Layer w0.2: HDR1.55@36.5,60.5 36.5,52.294 37,51.794 37,49 U1.B7@37.5,48.5
RAM1_DATA5: HDR1.51 U1.B8 | length 13.2
  Bottom Layer w0.2: 34.9,54.366 HDR1.51@34.9,60.5 ; 34.9,54.9 34.9,52.763 36,51.663 36,49 U1.B8@36.5,48.5
RAM1_DATA6: HDR1.47 U1.B9 | length 12.9
  Bottom Layer w0.2: HDR1.47@33.3,60.5 33.3,59.4 33.7,59 33.7,52.831 35,51.531 35,49 U1.B9@35.5,48.5
RAM1_DATA7: HDR1.43 U1.B10 | length 13.2
  Bottom Layer w0.2: HDR1.43@31.7,60.5 31.7,59.4 32.9,58.2 32.9,52.5 34,51.4 34,49 U1.B10@34.5,48.5
RAM1_OE: HDR1.39 U1.A12 | length 12.6
  Bottom Layer w0.2: HDR1.39@30.1,60.9 30.1,54.7 29.9,54.5 29.9,53.585 32.5,50.985 U1.A12@32.5,49.5
RAM1_WE: HDR1.61 U1.A6 | length 11.2
  Bottom Layer w0.2: U1.A6@38.5,49.5 38.5,50.731 38.9,51.131 HDR1.61@38.9,60.5
RAM_ADDR0: HDR1.21 U1.B16 | length 14.3
  Bottom Layer w0.2: HDR1.21@22.9,60.5 22.9,55.494 28,50.394 28,49 U1.B16@28.5,48.5
RAM_ADDR1: HDR1.25 U1.B15 | length 14.1
  Bottom Layer w0.2: HDR1.25@24.5,60.5 24.5,55.025 29,50.525 29,49 U1.B15@29.5,48.5
RAM_ADDR2: HDR1.29 U1.B14 | length 13.8
  Bottom Layer w0.2: HDR1.29@26.1,60.5 26.1,54.557 30,50.657 30,49 U1.B14@30.5,48.5
RAM_ADDR3: HDR1.33 U1.B13 | length 13.6
  Bottom Layer w0.2: HDR1.33@27.7,60.5 27.7,54.088 31,50.788 31,49 U1.B13@31.5,48.5
RAM_ADDR4: HDR1.65 U1.A5 | length 11.4
  Bottom Layer w0.2: U1.A5@39.5,49.5 39.5,50.6 40.5,51.6 HDR1.65@40.5,60.5
RAM_ADDR5: HDR1.69 U1.A4 | length 11.7
  Bottom Layer w0.2: U1.A4@40.5,49.5 40.5,50.231 42.1,51.831 HDR1.69@42.1,60.5
RAM_ADDR6: HDR1.73 U1.A3 | length 11.9
  Bottom Layer w0.2: U1.A3@41.5,49.5 43.7,51.7 43.7,52.3 HDR1.73@43.7,60.5
RAM_ADDR7: HDR1.77 U1.C1 | length 14.4
  Bottom Layer w0.2: U1.C1@43.5,47.5 44.1,47.5 45.3,48.7 45.7,49.1 45.7,52.1 45.3,52.5 45.3,52.6 HDR1.77@45.3,60.5
RAM_ADDR8: HDR1.75 U1.C2 | length 14.7
  Bottom Layer w0.2: U1.C2@42.5,47.5 43,48 43.9,48 44.9,49 44.9,51.3 44.5,51.7 HDR1.75@44.5,60.5
RAM_ADDR9: HDR1.71 U1.B3 | length 13
  Bottom Layer w0.2: U1.B3@41.5,48.5 41,49 41,50.166 42.9,52.066 HDR1.71@42.9,60.5
RAM_ADDR10: HDR1.67 U1.B4 | length 12.7
  Bottom Layer w0.2: U1.B4@40.5,48.5 40,49 40,50.297 41.3,51.597 HDR1.67@41.3,60.5
RAM_ADDR11: HDR1.63 U1.B5 | length 12.5
  Bottom Layer w0.2: U1.B5@39.5,48.5 39,49 39,50.666 39.7,51.366 HDR1.63@39.7,60.5
RAM_ADDR12: HDR1.59 U1.B6 | length 12.2
  Bottom Layer w0.2: HDR1.59@38.1,60.5 38.1,51.1 38,51 38,49 U1.B6@38.5,48.5
RAM_ADDR13: HDR1.35 U1.A13 | length 12.2
  Bottom Layer w0.2: HDR1.35@28.5,60.5 28.5,53.854 31.5,50.854 U1.A13@31.5,49.5
RAM_ADDR14: HDR1.31 U1.A14 | length 12.5
  Bottom Layer w0.2: HDR1.31@26.9,60.5 26.9,54.323 30.5,50.723 U1.A14@30.5,49.5
RAM_ADDR15: HDR1.27 U1.A15 | length 12.7
  Bottom Layer w0.2: HDR1.27@25.3,60.5 25.3,54.791 29.5,50.591 U1.A15@29.5,49.5
RAM_ADDR16: HDR1.23 U1.A16 | length 13
  Bottom Layer w0.2: HDR1.23@23.7,60.5 23.7,55.26 28.5,50.46 U1.A16@28.5,49.5
RAM_CS: HDR1.37 U1.B12 | length 13.3
  Bottom Layer w0.2: HDR1.37@29.3,60.5 29.3,53.62 32,50.92 32,49 U1.B12@32.5,48.5
RED0: HDR1.6 U1.D17 | length 28
  MidLayer1 w0.127: 26.5,47.5 26.5,48.5
  MidLayer1 w0.2: v1(16.5,68.6) 16.5,58.5 26.5,48.5 ; 26.5,47.5 v1(27,47)
  Bottom Layer w0.2: HDR1.6@16.5,67.3 v1(16.5,68.6) ; v1(27,47) U1.D17@27.5,46.5
RED1: HDR1.8 U1.C17 | length 26.6
  MidLayer1 w0.2: v1(17.3,68.6) 17.3,58.266 27,48.566 v1(27,48)
  Bottom Layer w0.2: HDR1.8@17.3,67.3 v1(17.3,68.6) ; v1(27,48) U1.C17@27.5,47.5
REF_CLK: HDR2.4 U1.AB12 | length 26.9
  Top Layer w0.2: v1(15.1,18.2) 27.4,18.2 v1(32.1,22.9)
  Bottom Layer w0.2: v1(15.1,18.2) 15.7,17.6 HDR2.4@15.7,16.5 ; v1(32.1,22.9) 32.3,22.9 32.7,23.3 32.7,24.1 32.5,24.3 U1.AB12@32.5,28.5
SCL: HDR2.5 U1.U19 | length 33.5
  MidLayer1 w0.127: 23.668,34.5 24.3,34.5
  MidLayer1 w0.2: v1(16.5,8.4) 16.5,23.894 19.4,26.794 19.4,31.8 22.1,34.5 23.668,34.5 ; 24.3,34.5 24.5,34.5 v1(25,34)
  Bottom Layer w0.2: v1(16.5,8.4) HDR2.5@16.5,9.7 ; v1(25,34) U1.U19@25.5,33.5
SDA: HDR2.3 U1.T20 | length 33.2
  MidLayer1 w0.2: v1(15.7,8.4) 15.7,23.66 19,26.96 19,32 22,35 v1(24,35)
  Bottom Layer w0.2: v1(15.7,8.4) HDR2.3@15.7,9.7 ; v1(24,35) U1.T20@24.5,34.5
SP0: HDR2.79 U1.W1 | length 25.9
  MidLayer1 w0.2: v1(46.1,8.4) v1(46.1,24.8)
  Bottom Layer w0.2: U1.W1@43.5,31.5 44.2,31.5 45.7,30 45.7,27.469 46.1,27.069 v1(46.1,24.8) ; v1(46.1,8.4) HDR2.79@46.1,9.7
SP1: HDR2.81 U1.V2 | length 28
  MidLayer1 w0.2: v1(46.9,8.4) 46.9,18.9 v1(46.9,24.8)
  Bottom Layer w0.2: U1.V2@42.5,32.5 43,32 44.3,32 46.1,30.2 46.1,27.634 46.9,26.834 v1(46.9,24.8) ; v1(46.9,8.4) HDR2.81@46.9,9.7
SP2: HDR2.83 U1.V1 | length 27.7
  MidLayer1 w0.2: v1(47.7,8.4) v1(47.7,24.8)
  Bottom Layer w0.2: U1.V1@43.5,32.5 44,32.5 44.4,32.5 46.5,30.4 46.5,27.8 47.7,26.6 v1(47.7,24.8) ; v1(47.7,8.4) HDR2.83@47.7,9.7
SP3: HDR2.85 U1.V4 | length 29.1
  MidLayer1 w0.2: v1(41,32) 41,31.8 41.4,31.4 42.1,31.4 48.5,25 v1(48.5,8.4)
  Bottom Layer w0.2: U1.V4@40.5,32.5 v1(41,32) ; v1(48.5,8.4) HDR2.85@48.5,9.7
SP4: HDR2.87 U1.V3 | length 28.7
  MidLayer1 w0.2: v1(42,32) 42.1,32 49.3,24.8 v1(49.3,8.4)
  Bottom Layer w0.2: U1.V3@41.5,32.5 v1(42,32) ; v1(49.3,8.4) HDR2.87@49.3,9.7
SP5: HDR2.89 U1.U2 | length 32.4
  MidLayer1 w0.2: v1(47.1,28.1) 49.7,25.5 49.7,9.3 50.1,8.9 v1@50.1,7.4
  Bottom Layer w0.2: U1.U2@42.5,33.5 43,33 44.5,33 46.9,30.6 46.9,28.3 v1(47.1,28.1) ; v1@50.1,7.4 HDR2.89@50.1,9.7
  other v1: 50.1,7.2
SP6: HDR2.91 U1.U1 | length 32.4
  MidLayer1 w0.2: v1@47.3,29.2 50.1,26.4 50.1,9.5 50.9,8.7 v1(50.9,7.4)
  Bottom Layer w0.2: U1.U1@43.5,33.5 44.6,33.5 47.3,30.8 47.3,29.2 v1(47.5,29) ; v1(50.9,7.4) HDR2.91@50.9,9.7
SP7: HDR2.92 U1.Y2 | length 18.7
  Bottom Layer w0.2: U1.Y2@42.5,30.5 43,30 43.9,30 44.5,29.4 44.5,27.5 43.7,26.7 43.7,24.8 50.9,17.6 HDR2.92@50.9,16.5
SP8: HDR2.90 U1.AB3 | length 15.6
  Bottom Layer w0.2: U1.AB3@41.5,28.5 41.5,26.2 50.1,17.6 HDR2.90@50.1,16.5
SP9: HDR2.88 U1.AA3 | length 16.6
  Bottom Layer w0.2: U1.AA3@41.5,29.5 41,29 41,25.9 49.3,17.6 HDR2.88@49.3,16.5
SP10: HDR2.86 U1.AB4 | length 15.3
  Bottom Layer w0.2: U1.AB4@40.5,28.5 40.5,25.6 48.5,17.6 HDR2.86@48.5,16.5
SP11: HDR2.84 U1.AB5 | length 15.4
  Bottom Layer w0.2: U1.AB5@39.5,28.5 39.5,25.8 47.7,17.6 HDR2.84@47.7,16.5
